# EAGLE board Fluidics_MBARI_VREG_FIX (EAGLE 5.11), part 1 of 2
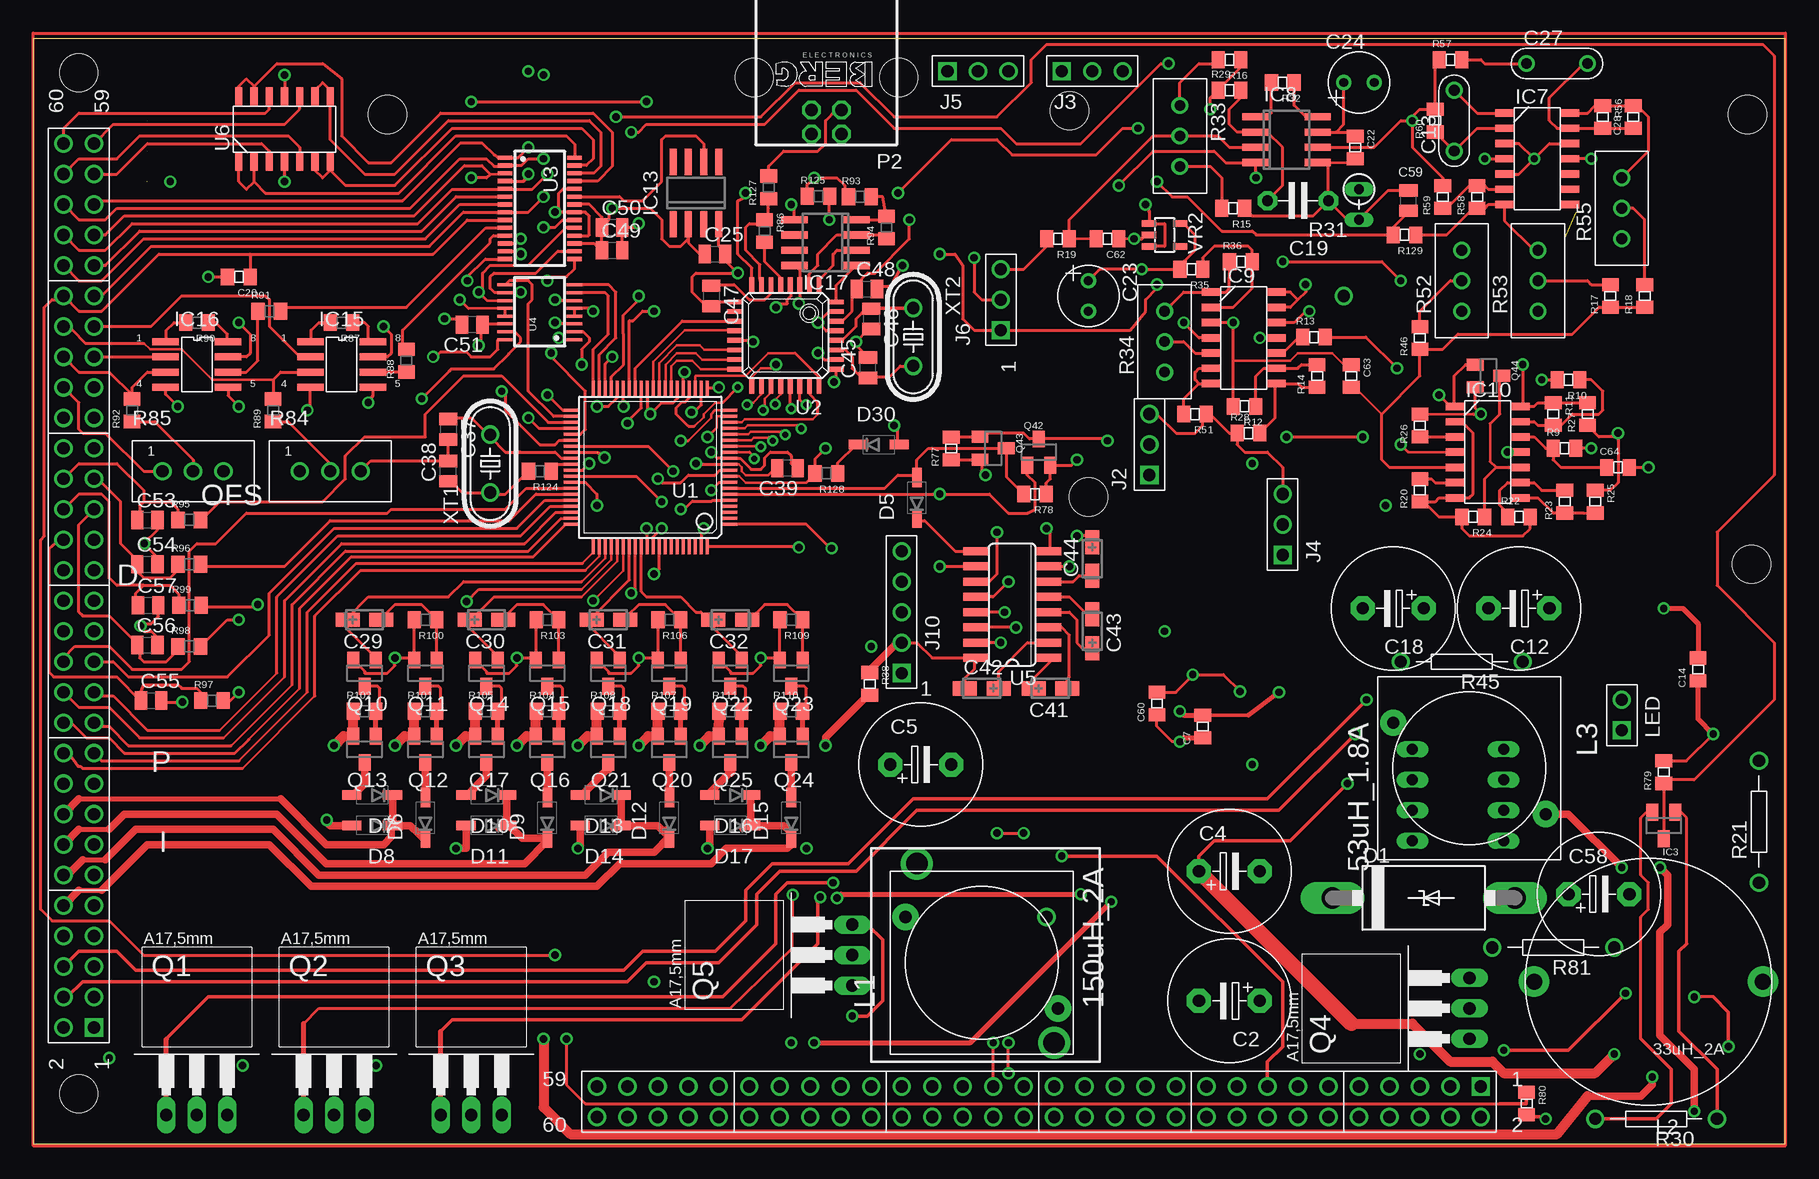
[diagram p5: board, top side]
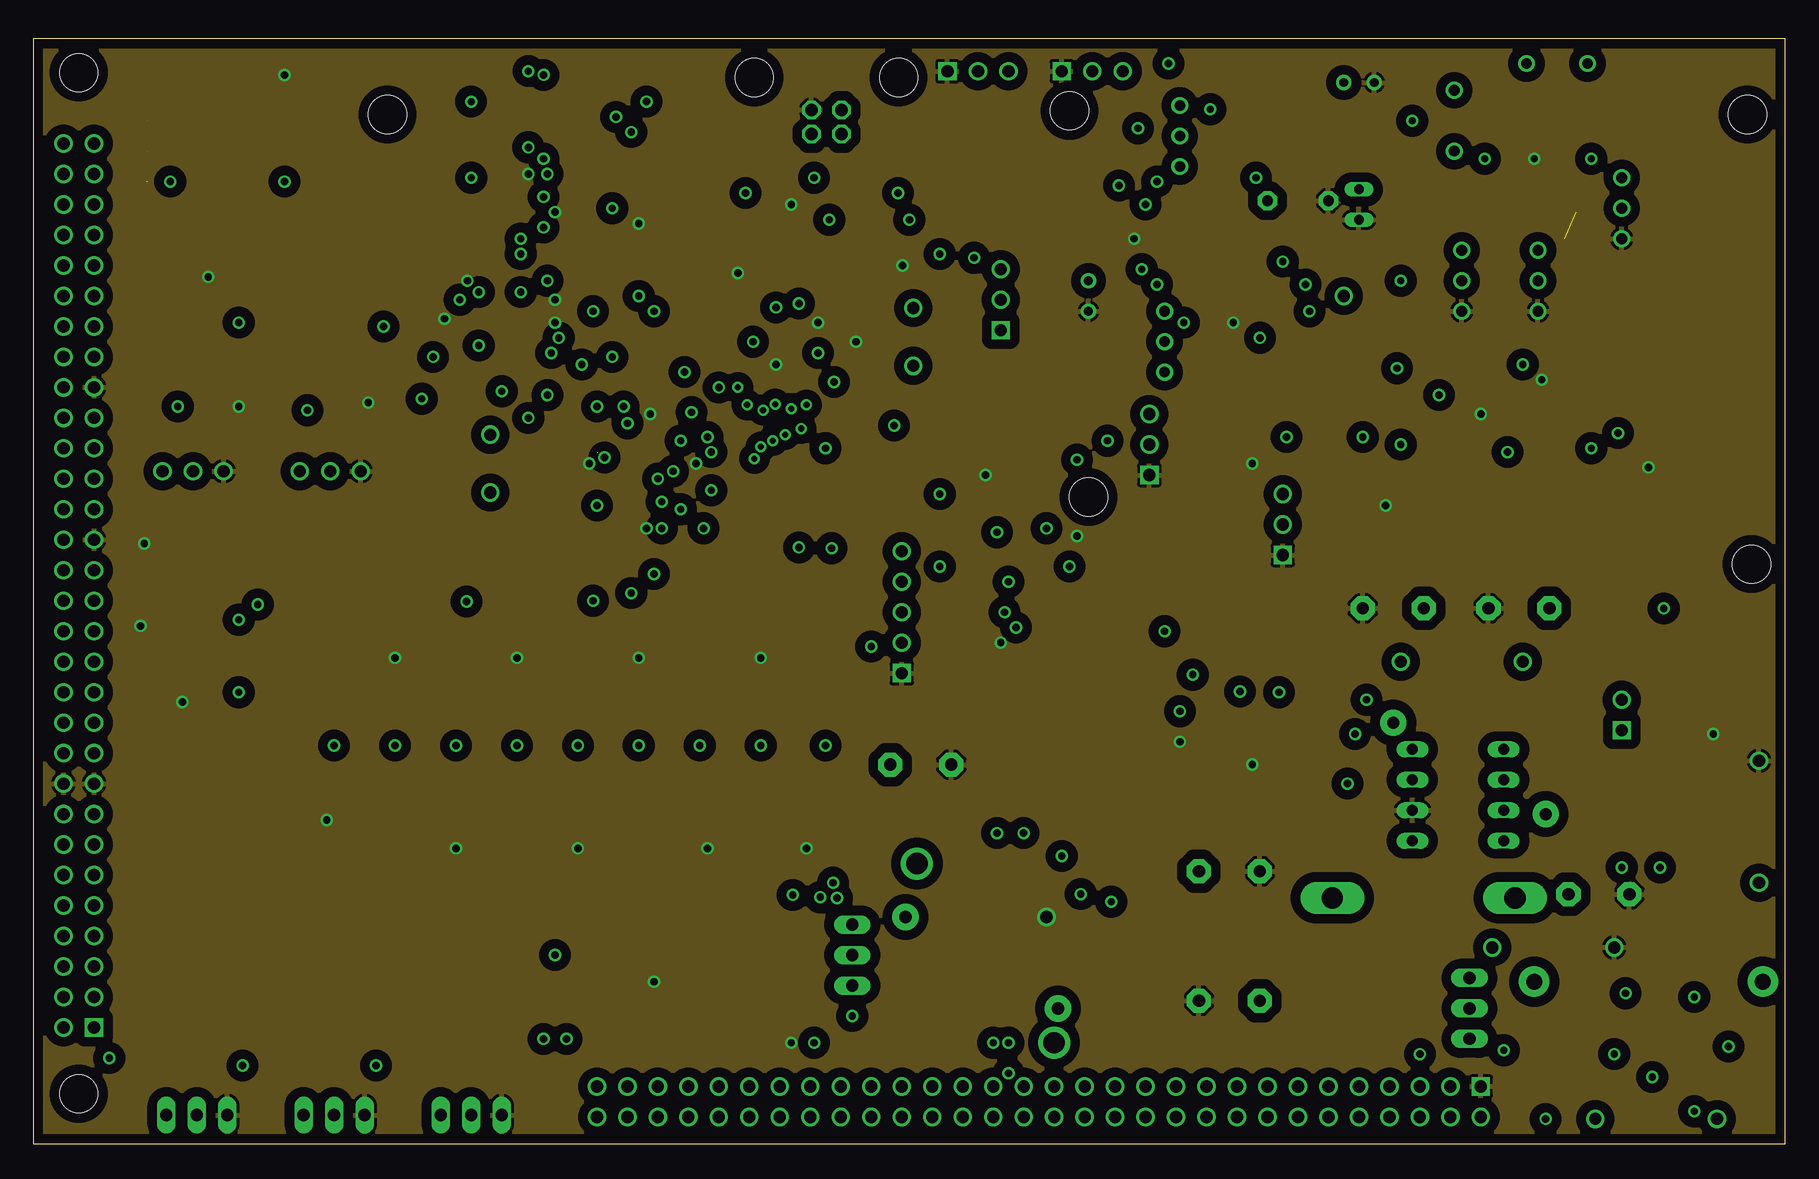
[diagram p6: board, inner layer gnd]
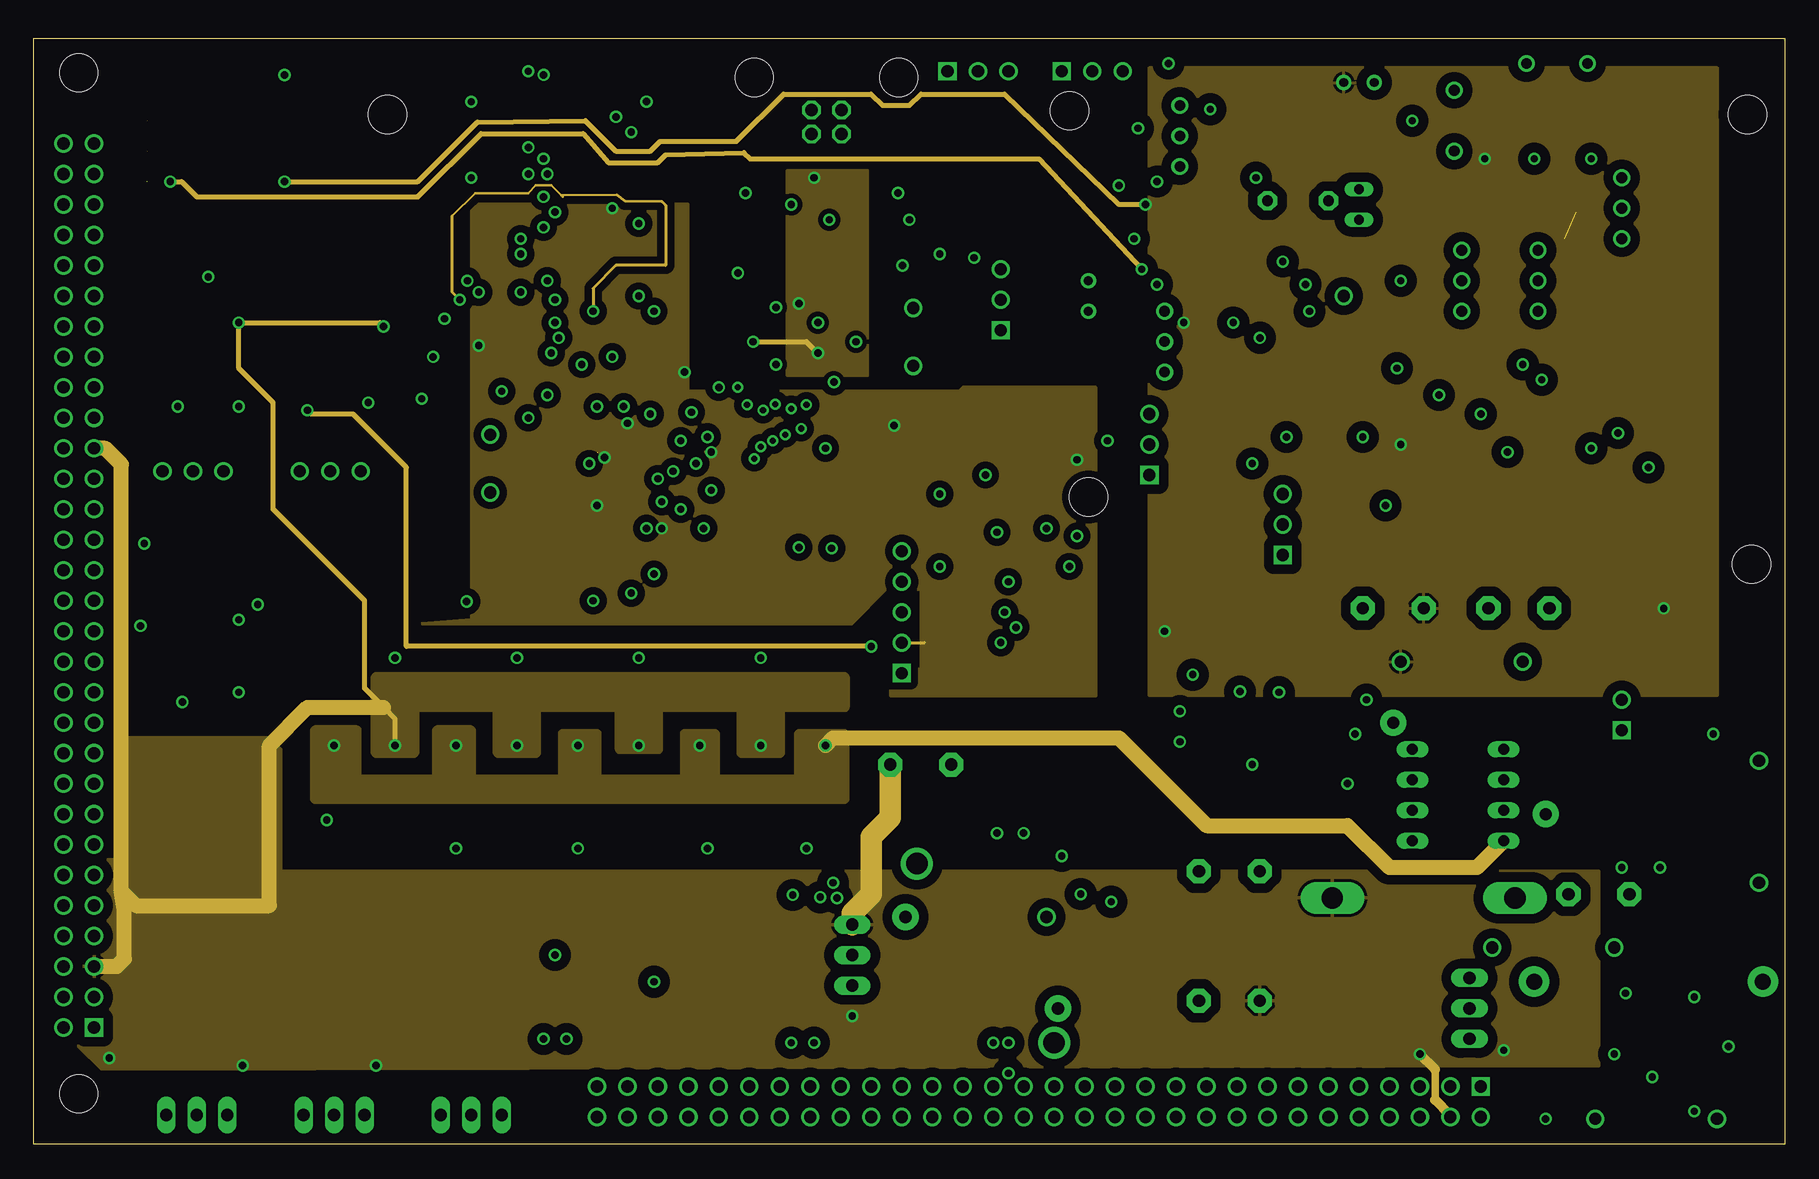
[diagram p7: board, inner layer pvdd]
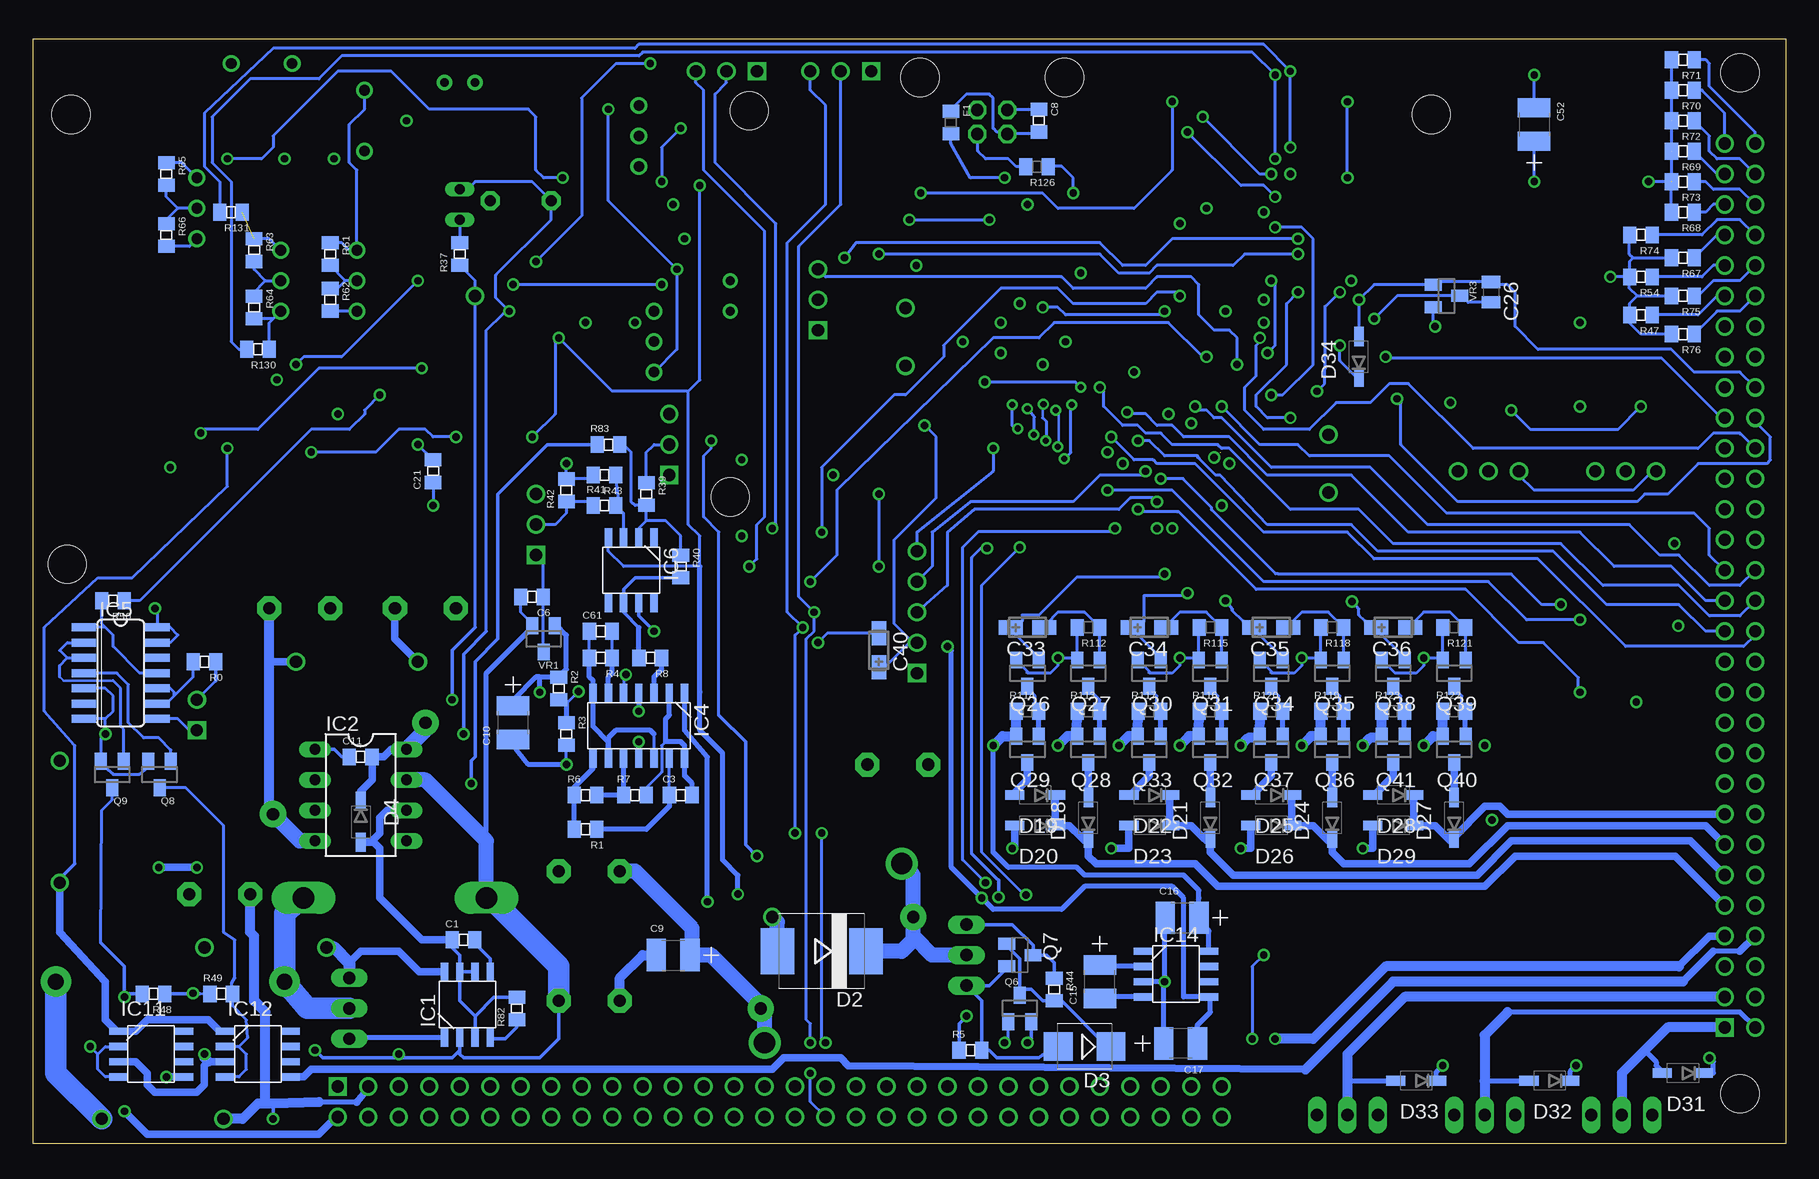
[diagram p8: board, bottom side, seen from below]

Size 146.03 x 92.06 mm. Coordinates in mm from the lower left corner, seen from the top.
Outline: 0,0 146.03,0 146.03,92.06 0,92.06 0,0
Copper layers (1*2*3*16): Top 0.035mm / dielectric 1.5mm / gnd 0.035mm / dielectric 0.15mm / pvdd 0.035mm / dielectric 0.2mm / Bottom 0.035mm
Design rules "default *": minimum track width 6mil, minimum drill 20mil, track to track 8mil, track to pad 8mil, pad to pad 7mil, via to via 7mil, smd to smd 0mil, copper to edge 8mil, drill to drill 6mil, minimum pad ring 8mil, minimum via ring 8mil, stop-mask expansion 0mil, vias tented up to drill 0mil, thermal gap 10mil
Net classes: 0 default: width 0.254 mm; 2 +5V: width 0.203 mm, drill 0.508 mm, clearance 0.203 mm
Holes 3.17 mm at 29.52,85.75 86.36,86.07 87.94,53.87 143.19,48.29 142.87,85.75 3.81,4.15 3.81,89.24

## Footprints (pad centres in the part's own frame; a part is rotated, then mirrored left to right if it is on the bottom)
0805 = smd 1.092 x 1.397: 1 -0.94,0; 2 0.94,0
ES-5 = drill 1.016 pad 2.007 octagon: 1 -2.54,0; 2 2.54,0
POLCAP1210 = smd 1.6 x 2.7: 1 -1.4,0; 2 1.4,0
C200 = drill 0.889 pad 1.397 round: 1 0,0; 2 5.08,0
C-5 = drill 0.889 pad 1.6 octagon: 1 -2.54,0; 2 2.54,0
C100P = drill 0.737 pad 1.27 round: + 0,0; - 2.54,0
C0805 = smd 1.016 x 1.524: 1 -0.85,0; 2 0.85,0
CT3216 = smd 2 x 1.2: + 1.4,0; - -1.4,0
C4111-15 = drill 1.778 long: A 7.62,0; C -7.62,0
SMC = smd 2.8 x 3.8: A 3.7,0; C -3.7,0
SMB = smd 2.4 x 2.4: A 2.2,0; C -2.2,0
SOD123 = smd 1.6 x 0.8: 1 -1.7,0; 2 1.7,0
SO8 = smd 1.524 x 0.61: 1 1.067,5.08; 2 1.067,3.81; 3 1.067,2.54; 4 1.067,1.27; 5 6.553,1.27; 6 6.553,2.54; 7 6.553,3.81; 8 6.553,5.08
DIL8 = drill 0.889 long: 1 -3.81,7.62; 2 -3.81,5.08; 3 -3.81,2.54; 4 -3.81,0; 5 3.81,0; 6 3.81,2.54; 7 3.81,5.08; 8 3.81,7.62
SOT23 = smd 1 x 1.4: 1 -0.95,-1.1; 2 0.95,-1.1; 3 0,1.1
SO-14 = smd 0.61 x 1.524: 1 -3.81,-2.794; 2 -2.54,-2.794; 3 -1.27,-2.794; 4 0,-2.794; 5 1.27,-2.794; 6 2.54,-2.794; 7 3.81,-2.794; 8 3.81,2.667; 9 2.54,2.667; 10 1.27,2.667; 11 0,2.667; 12 -1.27,2.667; 13 -2.54,2.667; 14 -3.81,2.667
SO14 = smd 0.66 x 2.032: 1 -3.81,-3.073; 2 -2.54,-3.073; 3 -1.27,-3.073; 4 0,-3.073; 5 1.27,-3.073; 6 2.54,-3.073; 7 3.81,-3.073; 8 3.81,3.073; 9 2.54,3.073; 10 1.27,3.073; 11 0,3.073; 12 -1.27,3.073; 13 -2.54,3.073; 14 -3.81,3.073
SO-8 = smd 0.61 x 1.524: 1 -1.27,-2.743; 2 0,-2.743; 3 1.27,-2.743; 4 2.54,-2.743; 5 2.54,2.743; 6 1.27,2.743; 7 0,2.743; 8 -1.27,2.743
INA141SOIC = smd 2.2 x 0.6: 1 2.48,5.715; 2 2.48,4.445; 3 2.48,3.175; 4 2.48,1.905; 5 7.68,1.905; 6 7.68,3.175; 7 7.68,4.445; 8 7.68,5.715
DUALFET1 = smd 1.524 x 0.61: 1 -2.743,2.54; 2 -2.743,1.27; 3 -2.743,0; 4 -2.743,-1.27; 5 2.743,-1.27; 6 2.743,0; 7 2.743,1.27; 8 2.743,2.54
SO8' = smd 0.6 x 2.2: 1 -1.905,-2.6; 2 -0.635,-2.6; 3 0.635,-2.6; 4 1.905,-2.6; 5 1.905,2.6; 6 0.635,2.6; 7 -0.635,2.6; 8 -1.905,2.6
INA141SOIC' = smd 2.2 x 0.6: 1 -2.6,1.905; 2 -2.6,0.635; 3 -2.6,-0.635; 4 -2.6,-1.905; 5 2.6,-1.905; 6 2.6,-0.635; 7 2.6,0.635; 8 2.6,1.905
SO-08 = smd 0.6 x 2.2: 1 -1.905,-2.6; 2 -0.635,-2.6; 3 0.635,-2.6; 4 1.905,-2.6; 5 1.905,2.6; 6 0.635,2.6; 7 -0.635,2.6; 8 -1.905,2.6
JUMP3 = drill 1.016 pad 1.524 square: 1 -2.54,0 | drill 1.016 pad 1.524 round: 2 0,0; 3 2.54,0
1X3 = drill 1.016 pad 1.524 square: 1 -2.54,0 | drill 1.016 pad 1.524 round: 2 0,0; 3 2.54,0
IDC3 = drill 1.016 square: 1 0,0 | drill 1.016 round: 2 2.54,0; 3 5.08,0
1X5 = drill 1.016 pad 1.524 square: 1 -5.08,0 | drill 1.016 pad 1.524 round: 2 -2.54,0; 3 0,0; 4 2.54,0; 5 5.08,0
INDUCTOR1 = drill 1.016 pad 2.184 round: P$1 3.81,1.27; P$2 11.43,13.97
INDUCTOR2 = drill 1.321 pad 2.54 round: P$1 -9.525,0; P$2 9.525,0
1X2 = drill 1.016 pad 1.524 square: 1 1.27,1.27 | drill 1.016 pad 1.524 round: 2 3.81,1.27
IDC60 = drill 1.016 square: 1 1.27,1.27 | drill 1.016 round: 2 1.27,3.81; 3 3.81,1.27; 4 3.81,3.81; 5 6.35,1.27; 6 6.35,3.81; 7 8.89,1.27; 8 8.89,3.81; 9 11.43,1.27; 10 11.43,3.81; 11 13.97,1.27; 12 13.97,3.81; 13 16.51,1.27; 14 16.51,3.81; 15 19.05,1.27; 16 19.05,3.81; 17 21.59,1.27; 18 21.59,3.81; 19 24.13,1.27; 20 24.13,3.81; 21 26.67,1.27; 22 26.67,3.81; 23 29.21,1.27; 24 29.21,3.81; 25 31.75,1.27; 26 31.75,3.81; 27 34.29,1.27; 28 34.29,3.81; 29 36.83,1.27; 30 36.83,3.81; 31 39.37,1.27; 32 39.37,3.81; 33 41.91,1.27; 34 41.91,3.81; 35 44.45,1.27; 36 44.45,3.81; 37 46.99,1.27; 38 46.99,3.81; 39 49.53,1.27; 40 49.53,3.81; 41 52.07,1.27; 42 52.07,3.81; 43 54.61,1.27; 44 54.61,3.81; 45 57.15,1.27; 46 57.15,3.81; 47 59.69,1.27; 48 59.69,3.81; 49 62.23,1.27; 50 62.23,3.81; 51 64.77,1.27; 52 64.77,3.81; 53 67.31,1.27; 54 67.31,3.81; 55 69.85,1.27; 56 69.85,3.81; 57 72.39,1.27; 58 72.39,3.81; 59 74.93,1.27; 60 74.93,3.81
PN61729 = drill 1.016 octagon: 1 1.25,4.71; 2 -1.25,4.71; 3 -1.25,2.71; 4 1.25,2.71 | hole 3.175: -6.02,0; 6.02,0
TO220 = drill 1.016 long: 1 -2.54,-6.35; 2 0,-6.35; 3 2.54,-6.35
SOT23-BEC = smd 1 x 1.4: B -0.95,-1.1; C 0,1.1; E 0.95,-1.1
R-10 = drill 1.016 pad 1.397 round: 1 -5.08,0; 2 5.08,0
RS-2,5 = drill 0.813 long: 1 -1.27,0; 2 1.27,0
TRIMPOT1 = drill 0.889 pad 1.397 round: 1 0,0; 2 5.08,0; 3 2.54,0
POT = drill 1.016 round: P$1 0,0; P$2 2.54,0; P$3 5.08,0
TQFP80 = smd 1.27 x 0.254: 1 -6.595,4.75; 2 -6.595,4.25; 3 -6.595,3.75; 4 -6.595,3.25; 5 -6.595,2.75; 6 -6.595,2.25; 7 -6.595,1.75; 8 -6.595,1.25; 9 -6.595,0.75; 10 -6.595,0.25; 11 -6.595,-0.25; 12 -6.595,-0.75; 13 -6.595,-1.25; 14 -6.595,-1.75; 15 -6.595,-2.25; 16 -6.595,-2.75; 17 -6.595,-3.25; 18 -6.595,-3.75; 19 -6.595,-4.25; 20 -6.595,-4.75; 41 6.595,-4.75; 42 6.595,-4.25; 43 6.595,-3.75; 44 6.595,-3.25; 45 6.595,-2.75; 46 6.595,-2.25; 47 6.595,-1.75; 48 6.595,-1.25; 49 6.595,-0.75; 50 6.595,-0.25; 51 6.595,0.25; 52 6.595,0.75; 53 6.595,1.25; 54 6.595,1.75; 55 6.595,2.25; 56 6.595,2.75; 57 6.595,3.25; 58 6.595,3.75; 59 6.595,4.25; 60 6.595,4.75 | smd 0.254 x 1.27: 21 -4.75,-6.595; 22 -4.25,-6.595; 23 -3.75,-6.595; 24 -3.25,-6.595; 25 -2.75,-6.595; 26 -2.25,-6.595; 27 -1.75,-6.595; 28 -1.25,-6.595; 29 -0.75,-6.595; 30 -0.25,-6.595; 31 0.25,-6.595; 32 0.75,-6.595; 33 1.25,-6.595; 34 1.75,-6.595; 35 2.25,-6.595; 36 2.75,-6.595; 37 3.25,-6.595; 38 3.75,-6.595; 39 4.25,-6.595; 40 4.75,-6.595; 61 4.75,6.595; 62 4.25,6.595; 63 3.75,6.595; 64 3.25,6.595; 65 2.75,6.595; 66 2.25,6.595; 67 1.75,6.595; 68 1.25,6.595; 69 0.75,6.595; 70 0.25,6.595; 71 -0.25,6.595; 72 -0.75,6.595; 73 -1.25,6.595; 74 -1.75,6.595; 75 -2.25,6.595; 76 -2.75,6.595; 77 -3.25,6.595; 78 -3.75,6.595; 79 -4.25,6.595; 80 -4.75,6.595
LQFP-32 = smd 0.4 x 1.2: 1 -2.8,-4.25; 2 -2,-4.25; 3 -1.2,-4.25; 4 -0.4,-4.25; 5 0.4,-4.25; 6 1.2,-4.25; 7 2,-4.25; 8 2.8,-4.25; 17 2.8,4.25; 18 2,4.25; 19 1.2,4.25; 20 0.4,4.25; 21 -0.4,4.25; 22 -1.2,4.25; 23 -2,4.25; 24 -2.8,4.25 | smd 1.2 x 0.4: 9 4.25,-2.8; 10 4.25,-2; 11 4.25,-1.2; 12 4.25,-0.4; 13 4.25,0.4; 14 4.25,1.2; 15 4.25,2; 16 4.25,2.8; 25 -4.25,2.8; 26 -4.25,2; 27 -4.25,1.2; 28 -4.25,0.4; 29 -4.25,-0.4; 30 -4.25,-1.2; 31 -4.25,-2; 32 -4.25,-2.8
TSSOP28 = smd 0.35 x 1.2: 1 -4.225,-2.9; 2 -3.575,-2.9; 3 -2.925,-2.9; 4 -2.275,-2.9; 5 -1.625,-2.9; 6 -0.975,-2.9; 7 -0.325,-2.9; 8 0.325,-2.9; 9 0.975,-2.9; 10 1.625,-2.9; 11 2.275,-2.9; 12 2.925,-2.9; 13 3.575,-2.9; 14 4.225,-2.9; 15 4.225,2.9; 16 3.575,2.9; 17 2.925,2.9; 18 2.275,2.9; 19 1.625,2.9; 20 0.975,2.9; 21 0.325,2.9; 22 -0.325,2.9; 23 -0.975,2.9; 24 -1.625,2.9; 25 -2.275,2.9; 26 -2.925,2.9; 27 -3.575,2.9; 28 -4.225,2.9
TSSOP16 = smd 0.254 x 1.27: 1 -2.275,-2.9; 2 -1.625,-2.9; 3 -0.975,-2.9; 4 -0.325,-2.9; 5 0.325,-2.9; 6 0.975,-2.9; 7 1.625,-2.9; 8 2.275,-2.9; 9 2.275,2.9; 10 1.625,2.9; 11 0.975,2.9; 12 0.325,2.9; 13 -0.325,2.9; 14 -0.975,2.9; 15 -1.625,2.9; 16 -2.275,2.9
SO16 = smd 0.66 x 2.032: 1 -4.445,-3.073; 2 -3.175,-3.073; 3 -1.905,-3.073; 4 -0.635,-3.073; 5 0.635,-3.073; 6 1.905,-3.073; 7 3.175,-3.073; 8 4.445,-3.073; 9 4.445,3.073; 10 3.175,3.073; 11 1.905,3.073; 12 0.635,3.073; 13 -0.635,3.073; 14 -1.905,3.073; 15 -3.175,3.073; 16 -4.445,3.073
SOT25 = smd 0.55 x 1.2: 1 -0.95,-1.3; 2 0,-1.3; 3 0.95,-1.3; 4 0.95,1.3; 5 -0.95,1.3
HC49/S = drill 1.016 round: 1 -2.413,0; 2 2.413,0

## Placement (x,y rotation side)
C1  0.1  [0805]  110.17,16.98 0 bottom
C2  100uF  [ES-5]  99.69,11.9 180 top
C3  .018  [0805]  92.07,29.05 0 bottom
C4  100uF  [ES-5]  99.69,22.7 0 top
C5  100uF  [ES-5]  73.97,31.59 0 top
C6  0.1uF  [0805]  104.45,45.55 180 bottom
C7  0.1uF  [0805]  97.47,34.76 90 top
C8  0.1uF  [0805]  62.22,85.24 270 bottom
C9  10uF  [POLCAP1210]  92.7,15.71 0 bottom
C10  10uF  [POLCAP1210]  106.04,35.08 90 bottom
C11  0.1uF  [0805]  118.74,32.22 0 bottom
C12  220uF  [ES-5]  123.82,44.6 180 top
C13  1uF  [C200]  118.42,82.7 90 top
C14  0.1  [0805]  138.74,39.52 90 top
C15  10uF  [POLCAP1210]  57.14,13.49 90 bottom
C16  10uF  [POLCAP1210]  50.29,18.82 0 bottom
C17  10uF  [POLCAP1210]  50.41,8.34 180 bottom
C18  220uF  [ES-5]  113.34,44.6 180 top
C19  0.47uF  [C-5]  105.41,78.57 180 top
C20  0.1uF  [0805]  17.14,72.22 180 top
C21  10uF  [0805]  112.71,56.03 90 bottom
C22  0.1uF  [0805]  110.17,83.02 270 top
C23  10uF  [C100P]  87.94,71.91 270 top
C24  10uF  [C100P]  109.22,88.42 0 top
C25  0.1uF  [C0805]  56.83,74.13 0 top
C26  0.1uF  [C0805]  24.54,70.95 270 bottom
C27  1.0uF  [C200]  124.45,90 0 top
C28  0.1uF  [0805]  133.34,85.56 90 top
C29  10uF  [CT3216]  27.62,43.65 180 top
C30  10uF  [CT3216]  37.78,43.65 180 top
C31  10uF  [CT3216]  47.94,43.65 180 top
C32  10uF  [CT3216]  58.1,43.65 180 top
C33  10uF  [CT3216]  63.18,43.02 180 bottom
C34  10uF  [CT3216]  53.02,43.02 180 bottom
C35  10uF  [CT3216]  42.86,43.02 180 bottom
C36  10uF  [CT3216]  32.7,43.02 180 bottom
C37  22pF  [C0805]  34.6,59.52 270 top
C38  22pF  [C0805]  34.6,56.03 90 top
C39  0.1uF  [C0805]  62.86,56.29 180 top
C40  10uF  [CT3216]  75.56,41.11 270 bottom
C41  10uF  [CT3216]  84.77,37.94 180 top
C42  10uF  [CT3216]  79.05,37.94 0 top
C43  10uF  [CT3216]  88.26,42.7 270 top
C44  10uF  [CT3216]  88.26,48.73 90 top
C45  22pF  [C0805]  69.58,64.66 90 top
C46  22pF  [C0805]  69.84,68.73 270 top
C47  33nF  [C0805]  56.51,70.64 270 top
C48  0.1uF  [C0805]  69.48,71.22 0 top
C49  0.1uF  [C0805]  48.25,74.45 0 top
C50  0.1uF  [C0805]  48.25,76.35 0 top
C51  0.1uF  [C0805]  36.6,68.24 180 top
C52  10uF  [POLCAP1210]  20.95,84.92 270 bottom
C53  0.1  [C0805]  9.52,51.97 0 top
C54  0.1  [C0805]  9.52,48.29 0 top
C55  0.1  [C0805]  9.84,36.92 0 top
C56  0.1  [C0805]  9.52,41.55 0 top
C57  0.1  [C0805]  9.58,44.86 0 top
C58  1000uF  [ES-5]  130.49,20.79 0 top
C59  0.1uF  [C0805]  114.61,78.57 90 top
C60  .1  [0805]  93.66,36.66 90 top
C61  .1  [0805]  98.74,42.7 0 bottom
C62  0.1uF  [0805]  89.53,75.4 180 top
C63  0.1uF  [0805]  109.85,63.97 270 top
C64  0.1  [0805]  132.08,56.35 0 top
D1  9_Amp_Shottky  [C4111-15]  115.88,20.47 0 top
D2  3_A Shottky  [SMC]  80.32,16.03 180 bottom
D3  1N5819HW  [SMB]  58.41,8.09 180 bottom
D4  1N5819HW  [SOD123]  118.74,26.82 270 bottom
D5  1N5819HW  [SOD123]  73.66,53.81 90 top
D6  1N5819HW  [SOD123]  32.7,27.14 90 top
D7  1N5819HW  [SOD123]  28.25,29.05 180 top
D8  1N5819HW  [SOD123]  28.25,26.51 180 top
D9  1N5819HW  [SOD123]  42.86,27.14 90 top
D10  1N5819HW  [SOD123]  37.78,29.05 180 top
D11  1N5819HW  [SOD123]  37.78,26.51 180 top
D12  1N5819HW  [SOD123]  53.02,27.14 90 top
D13  1N5819HW  [SOD123]  47.3,29.05 180 top
D14  1N5819HW  [SOD123]  47.3,26.51 180 top
D15  1N5819HW  [SOD123]  63.18,27.14 90 top
D16  1N5819HW  [SOD123]  58.1,29.05 180 top
D17  1N5819HW  [SOD123]  58.1,26.51 180 top
D18  1N5819HW  [SOD123]  58.1,27.14 90 bottom
D19  1N5819HW  [SOD123]  62.54,29.05 180 bottom
D20  1N5819HW  [SOD123]  62.54,26.51 180 bottom
D21  1N5819HW  [SOD123]  47.94,27.14 90 bottom
D22  1N5819HW  [SOD123]  53.02,29.05 180 bottom
D23  1N5819HW  [SOD123]  53.02,26.51 180 bottom
D24  1N5819HW  [SOD123]  37.78,27.14 90 bottom
D25  1N5819HW  [SOD123]  42.86,29.05 180 bottom
D26  1N5819HW  [SOD123]  42.86,26.51 180 bottom
D27  1N5819HW  [SOD123]  27.62,27.14 90 bottom
D28  1N5819HW  [SOD123]  32.7,29.05 180 bottom
D29  1N5819HW  [SOD123]  32.7,26.51 180 bottom
D30  1N5819HW  [SOD123]  70.48,58.26 0 top
D31  1N5819HW  [SOD123]  8.57,5.87 180 bottom
D32  1N5819HW  [SOD123]  19.68,5.23 180 bottom
D33  1N5819HW  [SOD123]  30.79,5.23 180 bottom
D34  [SOD123]  35.55,65.56 90 bottom
F1  FERRITE  [0805]  69.55,85.09 270 bottom
IC1  MAX1771ESA  [SO8]  106.68,7.77 90 bottom
IC2  LM2672-5  [DIL8]  118.74,25.23 0 bottom
IC3  ZXCT1009  [SOT23]  135.88,26.51 180 top
IC4  LT1802  [SO-14]  95.56,34.76 180 bottom
IC5  74HC14  [SO14]  138.74,39.2 270 bottom
IC6  MAX409  [SO-8]  95.56,47.78 180 bottom
IC7  TLC2254  [SO-14]  125.41,82.07 270 top
IC8  INA141  [INA141SOIC]  99.37,79.84 0 top
IC9  TLC2254  [SO-14]  100.96,67.14 270 top
IC10  TLC2254  [SO-14]  121.28,57.62 270 top
IC11  IRF7389  [DUALFET1]  136.2,6.82 0 bottom
IC12  IRF7389  [DUALFET1]  127.31,6.82 0 bottom
IC13  AD780  [SO8']  55.24,79.21 0 top
IC14  ICL7660  [SO8]  54.6,10.95 0 bottom
IC15  INA141  [INA141SOIC']  25.71,64.92 0 top
IC16  INA141  [INA141SOIC']  13.65,64.92 0 top
IC17  93-C46ASN  [SO-08]  66.04,75.08 90 top
J2  [JUMP3]  93.02,58.26 90 top
J3  [1X3]  88.26,89.37 0 top
J4  [1X3]  104.14,51.59 90 top
J5  [1X3]  78.73,89.37 0 top
J6  IDC3  [IDC3]  80.64,67.78 90 top
J10  [1X5]  72.39,44.29 90 top
L1  150uH_2A  [INDUCTOR1]  86.67,7.46 90 top
L2  33uH_2A  [INDUCTOR2]  134.62,13.49 180 top
L3  53uH_1.8A  [INDUCTOR1]  112.07,38.89 270 top
LED  1X2  [1X2]  133.66,33.17 90 top
P1  IDC60  [IDC60]  6.34,8.41 90 top
P2  USB_B  [PN61729]  66.11,88.85 180 top
P3  IDC60  [IDC60]  121.92,6.03 180 top
Q1  IRL3103L  [TO220]  13.65,8.73 0 top
Q2  IRL3103L  [TO220]  25.08,8.73 0 top
Q3  IRL3103L  [TO220]  36.51,8.73 0 top
Q4  IRL3103L  [TO220]  113.34,11.27 90 top
Q5  IRF4905L  [TO220]  61.91,15.71 90 top
Q6  BSS138  [SOT23]  63.81,11.27 0 bottom
Q7  FMMT491  [SOT23-BEC]  63.81,15.71 270 bottom
Q8  BSS138  [SOT23]  135.5,30.76 180 bottom
Q9  BSS138  [SOT23]  139.44,30.76 180 bottom
Q10  BSS138  [SOT23]  27.62,39.2 180 top
Q11  BSS138  [SOT23]  32.7,39.2 180 top
Q12  IRML6402  [SOT23]  32.7,32.86 180 top
Q13  IRML6402  [SOT23]  27.62,32.86 180 top
Q14  BSS138  [SOT23]  37.78,39.2 180 top
Q15  BSS138  [SOT23]  42.86,39.2 180 top
Q16  IRML6402  [SOT23]  42.86,32.86 180 top
Q17  IRML6402  [SOT23]  37.78,32.86 180 top
Q18  BSS138  [SOT23]  47.94,39.2 180 top
Q19  BSS138  [SOT23]  53.02,39.2 180 top
Q20  IRML6402  [SOT23]  53.02,32.86 180 top
Q21  IRML6402  [SOT23]  47.94,32.86 180 top
Q22  BSS138  [SOT23]  58.1,39.2 180 top
Q23  BSS138  [SOT23]  63.18,39.2 180 top
Q24  IRML6402  [SOT23]  63.18,32.86 180 top
Q25  IRML6402  [SOT23]  58.1,32.86 180 top
Q26  BSS138  [SOT23]  63.18,39.2 180 bottom
Q27  BSS138  [SOT23]  58.1,39.2 180 bottom
Q28  IRML6402  [SOT23]  58.1,32.86 180 bottom
Q29  IRML6402  [SOT23]  63.18,32.86 180 bottom
Q30  BSS138  [SOT23]  53.02,39.2 180 bottom
Q31  BSS138  [SOT23]  47.94,39.2 180 bottom
Q32  IRML6402  [SOT23]  47.94,32.86 180 bottom
Q33  IRML6402  [SOT23]  53.02,32.86 180 bottom
Q34  BSS138  [SOT23]  42.86,39.2 180 bottom
Q35  BSS138  [SOT23]  37.78,39.2 180 bottom
Q36  IRML6402  [SOT23]  37.78,32.86 180 bottom
Q37  IRML6402  [SOT23]  42.86,32.86 180 bottom
Q38  BSS138  [SOT23]  32.7,39.2 180 bottom
Q39  BSS138  [SOT23]  27.62,39.2 180 bottom
Q40  IRML6402  [SOT23]  27.62,32.86 180 bottom
Q41  IRML6402  [SOT23]  32.7,32.86 180 bottom
Q42  BSS84  [SOT23]  83.81,57.62 0 top
Q43  BSS138  [SOT23]  80.01,57.94 270 top
Q44  BSS84  [SOT23]  121.28,63.97 270 top
R0  470  [0805]  131.76,40.16 180 bottom
R1  3K  [0805]  100.01,26.19 180 bottom
R2  10K  [0805]  102.23,37.94 270 bottom
R3  10K  [0805]  101.59,34.12 270 bottom
R4  10K  [0805]  98.74,40.48 180 bottom
R5  380  [0805]  67.94,7.77 0 bottom
R6  11K  [0805]  100.01,29.05 0 bottom
R7  10K  [0805]  95.88,29.05 0 bottom
R8  10K  [0805]  94.61,40.48 180 bottom
R9  4.7K  [0805]  127.63,57.94 0 top
R10  3.0K  [0805]  127.95,63.65 180 top
R11  27.0K  [0805]  126.68,60.8 270 top
R12  20.0K  [0805]  100.96,61.43 180 top
R13  20K  [0805]  106.74,67.21 0 top
R14  100K  [0805]  106.99,63.97 90 top
R15  3.0K  [0805]  100.01,77.94 180 top
R16  3.0K  [0805]  99.69,90.32 180 top
R17  1.OM  [0805]  131.44,70.64 90 top
R18  1.0M  [0805]  134.3,70.64 90 top
R19  3.0K  [0805]  85.4,75.4 180 top
R20  20K  [0805]  115.56,54.45 90 top
R21  0.1  [R-10]  143.82,26.82 90 top
R22  20.0K  [0805]  123.82,52.22 0 top
R23  20.0K  [0805]  127.63,53.49 90 top
R24  20.0K  [0805]  120.01,52.22 180 top
R25  20.0K  [0805]  130.17,53.49 270 top
R26  20K  [0805]  115.56,59.84 90 top
R27  20.0K  [0805]  129.53,60.8 90 top
R28  3.0K  [0805]  101.28,59.21 0 top
R29  10.0K  [0805]  99.69,87.78 0 top
R30  .025_Ohm  [R-10]  135.25,2.06 180 top
R31  10K@25C  [RS-2,5]  110.48,78.26 270 top
R32  49.9  [0805]  104.14,88.42 180 top
R33  10K  [TRIMPOT1]  95.56,86.51 270 top
R34  10K  [TRIMPOT1]  94.29,64.29 90 top
R35  20.0K  [0805]  96.52,72.86 180 top
R36  20.0K  [0805]  100.64,73.49 0 top
R37  0_Ohm  [0805]  110.48,74.13 90 bottom
R38  1_Ohm  [0805]  69.72,38.32 270 top
R39  10K  [0805]  94.93,54.13 270 bottom
R40  OMIT  [0805]  92.07,48.09 270 bottom
R41  10K  [0805]  98.42,53.18 0 bottom
R42  100K  [0805]  101.59,54.45 90 bottom
R43  Optional  [0805]  98.42,55.72 180 bottom
R44  4.7k  [0805]  60.95,12.85 270 bottom
R45  1 Ohm  [R-10]  119.06,40.16 180 top
R46  1.0M  [0805]  115.56,67.14 90 top
R47  10K  [0805]  12.06,69.05 180 bottom
R48  4.7K  [0805]  136.01,12.47 180 bottom
R49  4.7K  [0805]  130.36,12.47 0 bottom
R50  4.7K  [0805]  139.38,45.24 180 bottom
R51  3.0K  [0805]  96.83,60.8 180 top
R52  10K  [TRIMPOT1]  119.06,69.37 90 top
R53  10K  [TRIMPOT1]  125.41,69.37 90 top
R54  10K  [0805]  12.06,72.22 180 bottom
R55  10K  [TRIMPOT1]  132.39,75.4 90 top
R56  10M  [0805]  130.81,85.56 270 top
R57  47K  [0805]  118.11,90.32 0 top
R58  100K  [0805]  120.33,78.89 90 top
R59  20.0K  [0805]  117.47,78.89 90 top
R60  10M  [0805]  116.84,85.24 90 top
R61  Optional  [0805]  121.28,74.13 270 bottom
R62  Optional  [0805]  121.28,70.32 270 bottom
R63  Optional  [0805]  127.63,74.45 270 bottom
R64  Optional  [0805]  127.63,69.68 270 bottom
R65  Optional  [0805]  134.93,80.8 270 bottom
R66  Optional  [0805]  134.93,75.72 270 bottom
R67  10K  [0805]  8.57,73.81 180 bottom
R68  10K  [0805]  8.57,77.62 180 bottom
R69  10K  [0805]  8.57,82.7 180 bottom
R70  10K  [0805]  8.57,87.78 180 bottom
R71  10K  [0805]  8.57,90.32 180 bottom
R72  10K  [0805]  8.57,85.24 180 bottom
R73  10K  [0805]  8.57,80.16 180 bottom
R74  10K  [0805]  12.06,75.72 180 bottom
R75  10K  [0805]  8.57,70.64 180 bottom
R76  10K  [0805]  8.57,67.46 180 bottom
R77  1K  [0805]  76.51,57.94 90 top
R78  4.7K  [0805]  83.5,54.13 180 top
R79  3.0K  [0805]  135.88,30.95 90 top
R80  30K  [0805]  124.45,3.33 270 top
R81  .025  [R-10]  126.68,16.35 180 top
R82  4.7K  [0805]  105.72,11.27 90 bottom
R83  100K  [0805]  98.1,58.26 0 bottom
R84  100k  [POT]  22.22,56.03 0 top
R85  100k  [POT]  10.79,56.03 0 top
R86  1k  [0805]  60.95,76.03 270 top
R87  GAIN  [0805]  25.71,68.41 180 top
R88  1k  [0805]  31.11,65.24 90 top
R89  100K  [0805]  20,61.11 90 top
R90  GAIN  [0805]  13.65,68.41 180 top
R91  1k  [0805]  19.68,69.37 0 top
R92  100K  [0805]  8.25,61.11 90 top
R93  10k  [0805]  68.89,78.89 0 top
R94  2.2k  [0805]  71.12,76.35 90 top
R95  10K  [0805]  13.01,51.97 0 top
R96  10K  [0805]  13.01,48.29 0 top
R97  10K  [0805]  14.92,36.92 0 top
R98  10K  [0805]  13.01,41.43 0 top
R99  10K  [0805]  13.08,44.86 0 top
R100  20K  [0805]  32.7,43.65 180 top
R101  4.7K  [0805]  32.7,36.03 0 top
R102  4.7K  [0805]  27.62,36.03 0 top
R103  20K  [0805]  42.86,43.65 180 top
R104  4.7K  [0805]  42.86,36.03 0 top
R105  4.7K  [0805]  37.78,36.03 0 top
R106  20K  [0805]  53.02,43.65 180 top
R107  4.7K  [0805]  53.02,36.03 0 top
R108  4.7K  [0805]  47.94,36.03 0 top
R109  20K  [0805]  63.18,43.65 180 top
R110  4.7K  [0805]  63.18,36.03 0 top
R111  4.7K  [0805]  58.1,36.03 0 top
R112  20K  [0805]  58.1,43.02 180 bottom
R113  4.7K  [0805]  58.1,36.03 0 bottom
R114  4.7K  [0805]  63.18,36.03 0 bottom
R115  20K  [0805]  47.94,43.02 180 bottom
R116  4.7K  [0805]  47.94,36.03 0 bottom
R117  4.7K  [0805]  53.02,36.03 0 bottom
R118  20K  [0805]  37.78,43.02 180 bottom
R119  4.7K  [0805]  37.78,36.03 0 bottom
R120  4.7K  [0805]  42.86,36.03 0 bottom
R121  20K  [0805]  27.62,43.02 180 bottom
R122  4.7K  [0805]  27.62,36.03 0 bottom
R123  4.7K  [0805]  32.7,36.03 0 bottom
R124  100  [0805]  42.22,56.03 180 top
R125  470  [0805]  65.45,78.94 0 top
R126  27  [0805]  62.39,81.41 180 bottom
R127  27  [0805]  61.3,79.69 90 top
R128  10k  [0805]  66.1,55.84 180 top
R129  10K  [0805]  114.3,75.72 180 top
R130  20K  [0805]  127.31,66.19 180 bottom
R131  20K  [0805]  129.53,77.62 180 bottom
U1  PIC18F8720  [TQFP80]  51.43,56.35 180 top
U2  FT245BM  [LQFP-32]  62.69,67.34 180 top
U3  AD7490  [TSSOP28]  42.22,77.94 270 top
U4  AD7398  [TSSOP16]  42.21,69.28 90 top
U5  MAX202  [SO16]  81.59,44.92 90 top
U6  TLC2254  [SO-14]  20.95,84.61 0 top
VR1  ZMR500FCT  [SOT23]  103.5,42.06 180 bottom
VR2  TS520533  [SOT25]  94.29,75.72 270 top
VR3  ZMR500FCT  [SOT23]  28.25,70.64 270 bottom
XT1  6_MHz  [HC49/S]  38.09,56.67 90 top
XT2  6_MHz  [HC49/S]  73.34,67.22 270 top

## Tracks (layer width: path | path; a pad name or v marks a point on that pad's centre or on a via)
1WIRE  (via drill 0.61)
  Top 0.254: 78.73,58.89 79.05,59.21 82.55,59.21 83.03,58.72 Q42.3 89.38,58.72 v89.53,58.57 | 78.73,58.89 Q43.1 | R77.2 78.73,58.88 78.73,58.89
  Top 0.305: v85.72,23.96 93.66,23.96 104.14,13.49 104.14,8.09 102.87,6.82 P3.15 102.87,4.6
  Bottom 0.254: v89.53,58.57 89.53,57.94 90.17,57.3 90.17,52.22 88.9,50.95 88.9,35.71
  Bottom 0.305: 88.9,35.71 86.67,33.49 86.67,24.92 v85.72,23.96
2.5V_REF
  Top 0.254: U3.23 48.87,78.91 49.21,78.57 50.79,78.57 52.38,80.16 52.38,83.65 52.7,83.97 55.24,83.97 55.88,83.34 IC13.6 55.88,81.75
5V_REF  (via drill 0.61)
  Top 0.203: 36.27,69.6 U4.12
  Top 0.254: v46.67,69.37 46.43,69.6 45.13,69.6 45.11,69.59 | v35.55,70.32 36.27,69.6 | 45.11,69.59 45.08,69.56 | 45.11,69.59 U4.5 45.11,69.08 45.08,69.05 45.11,69.02 U4.4 | U4.12 | U4.12 | U4.12 | U4.13 39.31,68.97 39.31,68.98 U4.12 | P1.44 3.81,61.75 3.81,59.52 4.12,59.21 6.03,59.21 9.2,56.03 R85.P$1
  pvdd 0.203: 44,79.02 43.17,79.84 41.9,79.84 41.27,79.21 36.82,79.21 34.92,77.3 | 44,79.02 44.13,78.89 | 44,79.02 48.64,79.08 49.34,78.51 52.38,78.51
  pvdd 0.254: v35.55,70.32 34.92,70.95 34.92,77.3 | v46.67,69.37 46.67,71.27 48.57,73.18 52.7,73.18 52.7,78.19 52.38,78.51
  Bottom 0.254: R85.P$1 11.11,56.03 12.69,54.45 20.95,54.45 22.22,55.72 R84.P$1 | 24.76,71.8 C26.1 | 24.76,71.8 28.99,71.8 29.21,71.59 VR3.1 34.29,71.59 v35.55,70.32 D34.2 | P1.44 3.81,64.29 7.62,64.29 9.52,66.19 20.63,66.19 22.54,68.1 22.54,70.95 23.17,71.59 24.44,71.59 24.76,71.91 24.76,71.8
+5V  (via drill 0.61)
  Top 0.203: 114.61,57.62 IC10.4
  Top 0.254: C22.1 110.17,83.97 110.48,84.29 108.58,84.29 | IC8.7 108.58,84.29 | C24.+ 109.22,84.92 108.58,84.29 | v120.96,82.07 IC7.4 | v20.95,80.16 U6.4 | IC9.4 97.15,67.14 v95.88,68.41 | v113.98,58.26 114.61,57.62 | v92.7,78.26 92.99,77.65 VR2.1 94.29,76.67 94.29,74.77 VR2.3
  Top 0.406: C14.2 138.74,43.33 137.47,44.6 v135.88,44.6
  pvdd 0.406: v92.7,78.26 90.48,78.26 80.96,87.46 73.97,87.46 73.02,86.51 70.8,86.51 69.84,87.46 62.54,87.46 58.61,83.53 52.26,83.53 51.43,82.7 48.57,82.7 46.03,85.24 37.02,85.12 32.06,80.16 v20.95,80.16
  Bottom 0.254: v20.95,80.16 C52.2 | v135.88,44.6 135.67,44.39 IC5.14 134.62,43.02 133.98,42.38 134.62,41.74 IC5.13 135.88,41.74 | C21.2 v113.98,58.26
  Bottom 0.305: IC6.7 95.56,43.97 v94.29,42.7
  Bottom 0.61: C18.1 115.88,42.06 R45.2
  pour pvdd (isolate 0.813): 93.02,37.3 93.02,89.69 140.33,89.69 140.33,37.3
+5V_B  (via drill 0.61)
  Top 0.254: 97.15,35.7 97.15,35.71 97.8,35.7
  Top 0.305: 97.8,35.7 101.27,35.7
  Top 0.406: C7.2 97.15,35.7 95.89,35.7 v95.56,36.03 | 101.27,35.7 v103.82,37.62
  Bottom 0.254: 102.55,43.33
  Bottom 0.305: 105.41,36.03 C10.2 106.04,36.98
  Bottom 0.406: 102.55,43.33 VR1.1 | IC4.4 v95.56,36.03 | 106.04,36.98 104.14,38.89 103.82,38.89 | 103.82,38.89 102.23,38.89 101.59,39.52 | 101.59,39.52 R2.1 | v103.82,37.62 103.82,38.89 | 101.59,39.52 101.59,42.38 102.55,43.33
+5V_IN  (via drill 0.61)
  Top 0.61: v138.43,2.69 138.43,6.18 135.57,9.04 135.57,17.62 136.2,18.25 136.2,22.38 v135.57,23.01 | v132.39,23.01 127.95,27.46 L3.P$2 | v66.04,33.17 66.04,33.87 69.54,37.38 R38.2
  Top 0.813: R111.1 57.14,34.12 Q25.2 56.34,33.95 v55.56,33.17 | R108.1 Q21.2 46.18,33.95 v45.4,33.17 | R105.1 Q17.2 36.02,33.95 v35.24,33.17 | R102.1 Q13.2 25.86,33.95 v25.08,33.17
  pvdd 1.27: v66.04,33.17 66.67,33.81 90.48,33.81 97.79,26.51 109.53,26.51 113.03,23.01 120.33,23.01 IC2.4
  Bottom 0.254: 48.89,18.57 C16.2 | 48.89,20.47
  Bottom 0.406: v66.04,33.17 66.04,24.28 64.77,23.01 59.05,23.01 58.41,22.38 50.16,22.38 48.89,21.11 48.89,20.47 | IC14.8 48.05,17.73 48.89,18.57 | C16.2 48.89,20.47
  Bottom 0.61: 126.36,40.16 R45.1 | P3.2 120.8,2.22 122.23,0.79 136.52,0.79 v138.43,2.69 | v132.39,23.01 v135.57,23.01
  Bottom 0.813: C12.1 126.36,40.16 126.36,27.78 L3.P$2 | R117.1 53.97,34.12 Q33.2 54.77,33.95 v55.56,33.17 | Q37.2 43.81,33.81 | 43.81,33.81 R120.1 | Q41.2 33.65,33.81 | 33.65,33.81 R123.1 | R114.1 64.13,34.12 Q29.2 65.25,33.95 v66.04,33.17 | 33.65,33.81 34.6,33.81 v35.24,33.17 | 43.81,33.81 44.76,33.81 v45.4,33.17
  Bottom 1.27: IC2.4 123.82,25.23 L3.P$2
  pour pvdd (isolate 0.61): 67.62,34.12 63.81,34.12 63.81,30.32 56.83,30.32 56.83,34.12 54.29,34.12 54.29,30.32 46.98,30.32 46.98,34.12 44.13,34.12 44.13,30.32 36.51,30.32 36.51,34.44 33.65,34.44 33.65,30.32 26.98,30.32 26.98,34.44 23.49,34.44 23.49,28.73 67.62,28.73
+12V  (via drill 0.61)
  Top 0.254: v29.21,68.1 29.84,67.46 29.84,65.88 29.52,65.56 IC15.7 28.25,65.56 | IC16.7 17.78,65.56 18.09,65.88 18.09,67.46 v17.14,68.41
  Top 0.305: v68.26,10.63 69.53,10.63 70.8,11.9 70.8,16.98 69.53,18.25 Q5.3 | v122.55,7.77 127.95,7.77 v132.71,12.54
  Top 0.813: R110.1 62.22,34.12 Q24.2 61.42,33.95 v60.64,33.17 | R107.1 Q20.2 51.26,33.95 v50.48,33.17 | R104.1 Q16.2 41.1,33.95 v40.32,33.17 | R101.1 Q12.2 30.94,33.95 v30.16,33.17
  pvdd 0.406: v29.21,68.1 28.89,68.41 v17.14,68.41 17.14,64.6 20,61.75 20,52.86 27.62,45.24 27.62,37.94 29.21,36.35 30.16,35.4 v30.16,33.17
  pvdd 0.61: 116.84,3.65 116.84,6.18
  pvdd 0.813: P3.4 118.11,2.38 116.84,3.65 | 116.84,6.18 v115.56,7.46
  pvdd 1.27: 29.21,36.35 22.86,36.35 19.68,33.17 19.68,19.84 8.57,19.84 7.36,21.04 | P1.39 6.03,57.94 7.36,56.6 7.36,21.04 | 7.36,21.04 7.62,19.52 7.62,15.39 6.98,14.76 P1.5
  pvdd 1.778: C5.1 71.43,27.14 69.84,25.55 69.84,20.79 68.26,19.2 Q5.3
  Bottom 0.254: C6.2 105.39,44.27 104.45,43.33 VR1.2 104.45,43.02 | R49.1 131.06,12.47 v132.71,12.54 | VR3.2 29.35,68.24 v29.21,68.1
  Bottom 0.305: C2.1 102.23,8.73 103.82,7.14 110.17,7.14 110.48,7.46 IC1.2 110.48,7.77 111.12,7.14 121.92,7.14 v122.55,7.77 | 62.71,16.03 Q7.C | 62.71,16.03 62.71,16.52 64.45,18.25 Q5.3 | R44.1 60.95,15.08 61.59,15.71 62.54,15.71 62.86,16.03 62.71,16.03 | R5.1 68.88,9.98 v68.26,10.63 | R48.1 132.14,12.47 v132.71,12.54
  Bottom 0.406: D32.1 17.98,5.98 v17.46,6.5 | D33.1 29.09,5.98 v28.57,6.5 | v6.34,7.14 6.03,6.82 6.03,5.87 D31.1 | 108.26,25.23 108.26,39.2 104.45,43.02
  Bottom 0.813: R113.1 59.05,34.12 Q28.2 59.85,33.95 v60.64,33.17 | R116.1 48.89,34.12 Q32.2 49.7,33.95 v50.48,33.17 | R119.1 38.73,34.12 Q36.2 39.53,33.95 v40.32,33.17 | R122.1 28.57,34.12 Q40.2 29.38,33.95 v30.16,33.17
  Bottom 1.27: IC2.7 113.34,30.32 108.26,25.23 D1.C
  Bottom 1.778: D1.C 107.95,20.47 102.23,14.76 C2.1
  pour pvdd (isolate 0.61): 67.62,36.35 62.22,36.35 62.22,32.54 59.05,32.54 59.05,36.35 52.06,36.35 52.06,32.86 48.89,32.86 48.89,36.35 41.9,36.35 41.9,32.54 38.73,32.54 38.73,36.35 31.75,36.35 31.75,32.54 28.57,32.54 28.57,38.89 67.62,38.89
  pour pvdd (isolate 0.813): 130.49,6.5 5.71,6.18 3.81,8.09 3.81,23.46 3.93,23.46 4.12,23.65 6.66,23.65 6.98,23.96 6.98,32.86 7.93,33.81 19.68,33.81 20.63,32.86 20.63,22.7 130.49,22.7
-5V_2  (via drill 0.61)
  Top 0.254: IC16.4 11.05,62.44 v12.06,61.43 | IC15.4 23.11,61.37 v22.86,61.11 | v102.23,67.14 IC9.11 | v101.91,80.48 101.85,80.54 IC8.4 99.37,81.75 98.42,82.7 93.34,82.7 v90.48,79.84 | v129.85,82.07 IC7.11 | v122.87,57.62 IC10.11 | v104.45,58.89 v110.8,58.89
  Top 0.406: v66.99,20.47 67.31,20.79 v87.31,20.79
  pvdd 0.406: v22.86,61.11 23.17,60.8 26.67,60.8 31.11,56.35 31.11,41.43 v69.84,41.43
  Bottom 0.254: 47.94,12.22 IC14.5 | IC6.4 98.1,49.37 96.83,48.09 90.48,48.09 90.48,50.63 91.44,51.59 91.44,62.7 | v22.86,61.11 21.27,59.52 13.96,59.52 v12.06,61.43 | v101.91,80.48 103.5,80.48 104.14,81.11 104.14,85.56 104.77,86.19 113.03,86.19 116.2,89.37 120.65,89.37 126.04,83.97 126.04,83.02 127,82.07 v129.85,82.07 | 91.44,62.7 90.48,63.65 v90.48,79.84 | v110.8,58.89 112.71,58.89 113.34,59.52 115.56,59.52 117.47,57.62 v122.87,57.62 | v104.45,58.89 102.55,60.8 102.55,66.83 v102.23,67.14 97.79,62.7 91.44,62.7
  Bottom 0.305: 90.48,37.62 90.48,37.3
  Bottom 0.406: C17.1 49.01,9.87 47.94,10.95 47.94,12.22 | IC14.5 50.16,12.22 50.16,20.47 51.11,21.43 58.41,21.43 60.32,19.52 66.04,19.52 v66.99,20.47 69.53,23.01 69.53,41.11 v69.84,41.43 | 90.48,48.09 90.48,37.62 90.48,34.44 88.58,32.54 88.58,23.65 87.31,22.38 v87.31,20.79
AD_NCS  (via drill 0.61)
  Top 0.254: U3.20 44.1,76.96 43.49,76.35 v42.54,76.35 | U1.41 44.14,61.1 v42.86,62.38
  Bottom 0.254: v42.86,62.38 41.9,62.38 39.36,64.92 39.36,75.4 40.32,76.35 v42.54,76.35
AN4  (via drill 0.61)
  Top 0.254: U3.9 36.17,76.96 33.33,74.13 18.09,74.13 | 18.09,74.13 10.47,74.13 5.71,69.37 3.81,69.37 P1.50 2.22,70.32 1.58,70.32 0.95,69.68 0.95,50.63 0.63,50.32 0.63,19.52 1.58,18.57 6.34,18.57 9.2,15.71 v43.49,15.71 | 122.23,3.33 46.03,3.33 44.45,4.92 v44.45,8.73 | C20.1 18.08,74.12 18.09,74.13
  Top 0.305: R80.1 124.44,3.31 122.23,3.33
  Bottom 0.254: R76.1 5.71,69.37 3.81,69.37 P1.50 | v44.45,8.73 44.45,14.76 v43.49,15.71
AN6
  Top 0.254: U3.7 39.36,78.27 39.36,78.26 35.55,78.26 32.7,75.4 9.2,75.4 5.71,71.91 3.81,71.91 P1.52
  Bottom 0.254: R75.1 7.62,70.32 6.03,71.91 3.81,71.91 P1.52
AN7
  Top 0.254: U3.6 35.26,78.91 32.38,76.03 8.88,76.03 6.03,73.18 P1.51
  Bottom 0.254: R54.1 6.98,72.22 6.03,73.18 P1.51
AN8  (via drill 0.61)
  Top 0.254: 39.36,79.53 U3.5 | 39.36,79.53 34.92,79.53 32.06,76.67 8.25,76.67 6.03,74.45 3.81,74.45 P1.54 | 135.88,30 IC3.3 | 39.36,79.53 41.59,79.53 v42.86,80.8 | v48.57,85.56 60.64,85.56 63.49,88.42 68.89,88.42 71.75,85.56 80.32,85.56 83.18,88.42 83.18,90.32 84.45,91.59 144.14,91.59 145.09,90.64 145.09,55.72 140.33,50.95 140.33,46.51 145.09,41.74 145.09,36.98 138.43,30.32 136.2,30.32 135.88,30 | 135.88,30 R79.1
  Bottom 0.254: R74.1 6.98,75.72 5.71,76.99 3.81,76.99 P1.54 | v42.86,80.8 43.81,80.8 v48.57,85.56
AN10  (via drill 0.6, 0.61)
  Top 0.254: P1.56 3.81,76.99 6.03,76.99 6.98,77.94 31.43,77.94 35.55,82.07 37.78,82.07 38.41,81.43 39.36,81.43 39.32,81.47 U3.2 40.72,81.52 41.27,82.07 v42.54,82.07
  Bottom 0.254: R73.1 6.66,80.16 6.03,79.53 3.81,79.53 P1.56 | v42.54,82.07 v42.54,89.05 44.45,90.96 95.25,90.96 95.56,90.64 120.33,90.64 122.23,88.73 127.95,88.73 131.12,85.56 131.12,81.75 129.53,80.16 129.55,66.84 128.9,66.19 R130.2
AN11  (via drill 0.6, 0.61)
  Top 0.254: P1.55 5.39,78.57 30.79,78.57 35.62,83.4 37.4,83.4 38.41,82.38 38.81,82.13 U3.1 40.41,82.16 v41.27,83.02
  Bottom 0.254: R68.1 6.66,77.62 6.03,78.26 P1.55 | R131.2 130.47,80.15 131.76,81.43 131.76,85.88 126.04,91.27 95.88,91.27 95.56,91.59 43.49,91.59 v41.27,89.37 v41.27,83.02
AN12
  Top 0.254: U3.28 45.12,83.29 44.45,83.97 35.24,83.97 30.48,79.21 19.36,79.21 18.41,80.16 | 18.41,80.16 U6.2 | 18.41,80.16 17.78,79.53 17.14,80.16 U6.1
AN13
  Top 0.254: U3.27 46.11,81.52 46.67,82.07 46.67,83.65 45.71,84.61 34.92,84.61 30.16,79.84 26.03,79.84 24.76,81.11 | 24.76,81.75 U6.7 24.76,81.11 | 24.76,81.11 24.12,80.48 23.49,81.11 U6.6 23.49,82.07
AN14
  Top 0.254: U3.26 46.73,80.86 47.3,81.43 47.3,84.29 46.35,85.24 34.6,85.24 30.16,80.8 27.62,80.8 24.76,83.65 U6.8 24.76,87.78 24.12,88.42 23.49,87.78 U6.9
AN15
  Top 0.254: U6.14 17.14,88.1 17.78,88.73 18.41,88.1 | 18.41,88.1 U6.13 | U3.25 47.04,80.21 48.25,81.43 48.25,84.29 46.67,85.88 33.97,85.88 29.84,81.75 27.94,81.75 25.71,83.97 25.71,88.73 24.12,90 20.32,90 18.41,88.1
AV1
  Bottom 0.254: Q26.3 63.18,37.94 62.54,37.3 62.54,36.03
  Bottom 0.406: 62.54,36.03 R114.2 62.24,34.43 62.54,34.12 62.37,33.95 Q29.1
AV2
  Bottom 0.254: Q30.3 53.02,37.94 52.38,37.3 52.38,36.03
  Bottom 0.406: 52.38,36.03 R117.2 52.08,34.43 52.38,34.12 52.21,33.95 Q33.1
AV3
  Bottom 0.254: Q34.3 42.86,37.94 42.22,37.3 42.22,36.03
  Bottom 0.406: 42.22,36.03 R120.2 41.92,34.43 42.22,34.12 42.05,33.95 Q37.1
AV4
  Bottom 0.254: Q38.3 32.7,37.94 32.06,37.3 32.06,36.03
  Bottom 0.406: 32.06,36.03 R123.2 31.76,34.43 32.06,34.12 31.89,33.95 Q41.1
AV5
  Top 0.254: Q10.3 28.72,38.11 28.89,37.94 28.89,36.03
  Top 0.406: 28.89,36.03 R102.2 28.56,33.81 28.57,33.81 | 28.57,33.81 | Q13.1 28.57,33.81
AV6
  Top 0.254: Q14.3 38.88,38.11 39.05,37.94 39.05,36.03
  Top 0.406: 39.05,36.03 R105.2 38.72,33.81 38.73,33.81 | 38.73,33.81 | Q17.1 38.73,33.81
AV7
  Top 0.254: Q18.3 49.04,38.11 49.21,37.94 49.21,36.03
  Top 0.406: 49.21,36.03 R108.2 48.88,33.81 48.89,33.81 | 48.89,33.81 | Q21.1 48.89,33.81
AV8
  Top 0.254: Q22.3 59.2,38.11 59.37,37.94 59.37,36.03
  Top 0.406: 59.37,36.03 R111.2 59.04,33.81 59.05,33.81 | 59.05,33.81 | Q25.1 59.05,33.81
AVCC  (via drill 0.61 pad 1.02)
  Top 0.254: R125.2 66.39,78.93 66.35,78.89 v66.35,76.99 | U2.30 67.43,68.54 68.26,69.37 68.26,70.64 68.63,71.01 C48.1 68.63,71.54 68.58,71.59 69.53,72.54 70.16,72.54 73.02,75.4 v73.02,76.99
  Bottom 0.254: v73.02,76.99 v66.35,76.99
D
  Top 0.254: R18.2 134.3,76.99 133.34,77.94 R55.3
  Bottom 0.254: R65.2 134.93,78.89 133.98,77.94 | R55.3 133.98,77.94 | R66.1 134.93,76.99 133.98,77.94
DA_NCS
  Top 0.254: U4.9 39.33,71.55 39.68,71.91 41.27,71.91 41.59,71.59 41.59,70.32 41.27,70 41.27,62.7 43.37,60.6 U1.42
DA_NLDAC
  Top 0.254: 46.67,62.96 U1.40 46.68,66.2 47.94,67.46 47.94,70.64 47.67,70.9 U4.7
DA_NRS
  Top 0.254: U1.39 47.18,65.75 48.57,67.14 48.57,70.95 47.97,71.55 U4.8
DA_OUT_B  (via drill 0.61)
  Top 0.254: U4.1 43.95,67 v43.81,67.14
  Bottom 0.254: v43.81,67.14 43.81,66.83 44.13,66.51 44.13,63.97 45.08,63.02 45.08,61.11 43.49,59.52 39.68,59.52 37.46,61.75 34.6,61.75 33.02,63.34 31.43,63.34 26.03,57.94 7.3,57.94 6.03,59.21 3.87,59.21 3.81,59.14 3.77,59.18 | P1.40 3.77,59.18 | 3.77,59.18 3.81,59.21 | 3.77,59.18
DA_OUT_C  (via drill 0.61)
  Top 0.254: v33.33,65.56 33.78,65.8 33.95,65.98 36.09,65.98 36.51,65.56 38.09,65.56 38.73,66.19 38.73,66.95 38.75,66.98 39.2,66.98 39.24,67.02 39.25,67 U4.16
  Bottom 0.254: P1.41 5.33,60.47 10.31,65.44 32.89,65.44 v33.33,65.56
DA_OUT_D  (via drill 0.61)
  Top 0.254: U4.15 40.13,67.65 40.63,67.14 40.63,66.83 39.68,65.88 39.64,65.8 38.4,64.55 34.84,64.55 34.67,64.38 34.6,64.29 v32.38,62.06
  Bottom 0.254: v32.38,62.06 32.06,61.75 32.06,58.26 27.3,53.49 12.38,53.49 11.74,54.13 9.84,54.13 7.3,56.67 1.58,56.67 1.27,56.98 1.27,58.89 2.54,60.16 P1.42
DB0  (via drill 0.51, 0.61)
  Top 0.203: 57.46,61.75 56.83,61.75 55.88,60.8 55.88,60.54 55.11,59.78
  Top 0.254: 57.46,61.75 v58.73,63.02 | 66.73,63.4 66.67,63.34 | v66.73,63.46 66.73,63.4 | U2.25 66.95,63.61 66.73,63.4 | 55.11,59.78 54.6,59.78 53.59,60.8 53.59,61.3 54.1,61.81 54.35,61.81 54.68,62.14 U1.24
  Bottom 0.254: v66.73,63.46 59.18,63.46 v58.73,63.02
DB1
  Top 0.203: U1.23 55.18,63.91 55.24,63.97 59.37,63.97 61.27,65.88 63.49,65.88
  Top 0.254: U2.24 65.47,63.09 65.47,63.9 63.49,65.88
DB2
  Top 0.203: U1.18 59.05,60.1 59.3,60.35 64.95,60.35 65.4,60.8
  Top 0.254: 65.4,60.8 65.4,61.75 64.77,62.38 64.77,63.02 U2.23
DB3  (via drill 0.51 pad 0.71)
  Top 0.203: U1.17 59.32,59.6 59.56,59.84 63.81,59.84
  Top 0.254: 64.07,59.59 64.13,59.52 | 64.07,59.59 v64,59.59 | 63.81,59.84 64.07,59.59 | v64.45,61.56 64.45,61.43 63.89,61.98 U2.22
  Bottom 0.254: v64,59.59 64.07,59.59 64.13,59.52 64.45,59.84 v64.45,61.56
DB4  (via drill 0.51 pad 0.71)
  Top 0.203: U1.16 59.58,59.1 59.81,59.33 62.41,59.33
  Top 0.254: 62.41,59.33 v62.67,59.08 | v63.18,61.24 63.18,61.11 63.09,61.2 U2.21
  Bottom 0.254: v62.67,59.08 62.54,59.21 62.61,59.27 62.61,60.54 63.11,61.18 63.18,61.11 v63.18,61.24
DB5  (via drill 0.51, 0.51 pad 0.71)
  Top 0.203: U1.15 59.84,58.6 60.07,58.83 61.34,58.83 | v61.84,61.62 61.84,62 62.29,62.45 U2.20
  Top 0.254: v61.65,58.57 61.59,58.57 61.34,58.83
  Bottom 0.203: 61.91,60.48 61.91,61.75
  Bottom 0.254: 61.91,61.75 61.84,61.81 v61.84,61.62 | 61.91,60.48 61.59,60.16 61.59,58.57 v61.65,58.57
DB6  (via drill 0.51, 0.51 pad 0.71)
  Top 0.203: U2.19 61.49,62.61 60.95,62.06 60.95,61.11 | U1.14 60.48,58.1
  Top 0.254: v60.83,61.11 60.95,61.11 | v60.64,58.06 60.64,58.26 60.48,58.1
  Bottom 0.203: 60.64,61.11 v60.83,61.11 | 60.57,58.32 60.57,61.05
  Bottom 0.254: 60.57,61.05 60.64,61.11 | v60.64,58.06 60.64,58.26 60.57,58.32
DB7  (via drill 0.51, 0.51 pad 0.61)
  Top 0.203: U1.13 59.7,57.6 60.1,57.21 | U2.18 60.7,62.44 60,61.75 59.68,61.75
  Top 0.254: 59.37,61.43 v59.49,61.56 59.68,61.75 | 59.7,57.6 59.68,57.62 | 60.1,57.21 v60.1,57.08
  Bottom 0.254: 59.49,61.62 59.37,61.75 | 59.49,61.62 v59.49,61.56 | 59.49,61.62 59.56,61.56 59.56,57.59 60.07,57.08 v60.1,57.08
EECS
  Top 0.254: IC17.1 68.58,73.18 66.95,71.55 U2.32
EEDATA
  Top 0.254: U2.2 64.7,72.47 65.4,73.18 65.4,74.13 66.99,75.72 IC17.3 70.48,75.72 70.8,75.4 R94.1
EEDOUT
  Top 0.254: IC17.4 70.48,76.99 70.8,77.3 R94.2 70.8,78.89 R93.2
EESK
  Top 0.254: U2.1 65.5,72 66.67,73.18 66.67,74.13 66.99,74.45 IC17.2
FET_SW1_CTRL  (via drill 0.61)
  Top 0.254: U1.79 55.68,51.08 v55.88,51.27
  Top 0.305: 11.11,8.73 14.6,12.22 57.46,12.22 61.91,16.66 61.91,20.79 62.86,21.74 v66.67,21.74
  Top 0.406: Q1.1 11.11,8.73
  Bottom 0.254: v55.88,51.27 56.26,51.02 67.24,51.02 68.58,49.68 68.58,23.65 v66.67,21.74
FET_SW2_CTRL  (via drill 0.61)
  Top 0.254: 22.54,10 23.81,11.27 58.1,11.27 63.24,16.28 v63.3,20.73 | U1.80 63.74,49.76 v63.81,49.68
  Top 0.406: Q2.1 22.54,10
  Bottom 0.254: v63.81,49.68 66.99,46.51 66.99,24.28 63.43,20.73 v63.3,20.73
FET_SW3_CTRL  (via drill 0.61)
  Top 0.254: v66.54,49.62 66.61,49.62 66.35,49.68 64.44,51.6 U1.1
  Top 0.305: 33.97,9.36 34.92,10.31 59.05,10.31 65.4,16.66 65.4,20.16
  Top 0.406: Q3.1 33.97,9.36 | v65.59,20.54 65.59,20.35 65.4,20.16
  Bottom 0.254: v66.54,49.62 67.05,49.62 67.81,48.86 67.81,24.16
  Bottom 0.305: 67.81,24.16 66.04,22.38 65.72,22.06 65.59,21.93 v65.59,20.54
GND  (via drill 0.61, 0.61 pad 0.71, 0.61 pad 1.02, 1.02)
  Top 0.203: U1.11 58.8,56.6 59.05,56.35 59.05,56.03 59.37,55.72 61.27,55.72 | U2.17 59.89,63.86 60.64,64.6 61.59,64.6 v61.91,64.92 | R26.2 120,60.78 | C62.1 v91.75,75.4 | C63.1 109.23,64.91 108.26,65.88 105.41,65.88 104.77,65.24 100.02,65.24 100.01,65.24
  Top 0.254: 62.22,40.48 62.23,40.48 Q23.2 62.23,40.47 62.22,40.48 | 62.22,40.48 v60.64,40.48 60.64,39.84 60,39.2 58.1,39.2 58.1,39.36 Q22.2 | 52.06,40.48 52.07,40.48 Q19.2 52.07,40.47 52.06,40.48 | 52.06,40.48 v50.48,40.48 50.48,39.84 49.84,39.2 47.94,39.2 47.94,39.36 Q18.2 | 41.9,40.48 41.91,40.48 Q15.2 41.91,40.47 41.9,40.48 | 41.9,40.48 v40.32,40.48 40.32,39.84 39.68,39.2 37.78,39.2 37.78,39.36 Q14.2 | 31.75,40.48 Q11.2 31.75,40.47 31.75,40.48 | 31.75,40.48 v30.16,40.48 30.16,39.84 29.52,39.2 27.62,39.2 27.62,39.36 Q10.2 | R109.2 62.24,40.49 62.22,40.48 | R106.2 52.08,40.49 52.06,40.48 | R103.2 41.92,40.49 41.9,40.48 | R100.2 31.76,40.49 31.75,40.48 | C37.2 C38.2 28.15,56.88 R84.P$3 | U1.70 51.18,51.2 v51.11,51.27 | U1.11 55.31,56.6 v55.24,56.67 | v50.48,76.67 50.16,76.35 C50.2 49.1,74.55 49.21,74.45 C49.2 | U2.29 66.08,67.73 v65.4,68.41 66.32,69.34 U2.31 | U3.4 40.9,80.21 v41.27,80.8 | U3.14 37.68,73.71 36.19,72.22 v36.19,71.91 | U1.31 51.18,61.05 v51.43,60.8 52.38,61.75 53.34,61.75 53.68,62.09 U1.26 | C39.2 61.97,56.29 61.91,56.35 61.27,55.72 | U1.51 45.78,56.1 v46.35,56.67 | C53.2 10.37,51.17 9.27,50.06 | 9.27,50.06 9.2,50 10.37,48.83 C54.2 | v9.27,50 9.27,50.06 | C57.2 10.43,43.93 9.84,43.33 8.88,43.33 8.95,43.27 v8.95,43.14 8.95,43.08 8.88,43.02 9.2,42.7 9.84,42.7 10.37,42.16 C56.2 | 10.85,36.6 10.69,36.77 C55.2 10.73,36.92 10.79,36.98 10.98,36.79 v12.44,36.79 | IC17.5 63.43,78 v63.18,78.26 | IC16.5 16.25,62.32 v17.14,61.43 | IC15.5 28.31,62.32 v27.94,61.75 | C51.2 35.7,68.55 35.55,68.41 35.24,68.73 v34.28,68.73 | C46.2 69.63,67.88 v68.58,66.83 68.58,66.51 C45.2 | C48.2 70.33,71.44 71.5,71.44 71.5,71.46 v72.45,73.18
  Top 0.254: U3.18 46.3,75.66 46.35,75.72 46.35,77.3 46.03,77.62 45.08,77.62 45.09,77.61 U3.21 v43.5,77.61 v43.49,77.62 43.81,77.94 43.81,79.21 44.16,79.56 U3.24 | U4.6 43.56,70.25 v43.49,70.32 | U4.3 43.6,68.3 v43.49,68.41 | v80.64,41.74 U5.15 | 57.78,74.13 C25.2 | IC13.4 57.14,74.77 57.78,74.13 | U2.9 56.96,70.13 56.51,69.68 C47.2 56.29,69.79 56.19,69.68 54.92,70.95 54.92,72.22 55.24,72.54 v58.73,72.54 57.78,73.49 57.78,74.13 | C19.1 106.68,77.3 101.59,77.3 100.96,77.94 R15.1 | C19.1 107.95,81.75 | 107.95,81.75 IC8.5 | C22.2 109.86,81.76 107.95,81.75 | v125.09,82.07 126.36,83.34 IC7.12 | IC7.5 123.82,80.8 v125.09,82.07 | IC7.3 123.82,83.34 v125.09,82.07 | 120,60.78 v120.65,60.8 120.18,61.26 Q44.2 | IC9.3 v100.01,68.41 100.02,68.4 100.02,65.24 R12.2 | C19.1 109.53,76.99 R31.2 112.92,79.42 C59.2 | R10.2 127.01,63.96 127,63.97 126.68,63.65 v125.73,63.65 | C44.+ 88.26,50.32 87.94,50.63 v86.99,50.63 | v20.95,89.05 U6.11 | 78.73,56.99 78.73,56.98 | 78.73,56.99 Q43.2 78.91,56.81 79.05,56.67 79.05,56.03 v79.37,55.72 | R77.1 78.73,57 78.73,56.99 | R79.2 137.78,31.89 v140.01,34.12 | v14.6,72.22 C20.2 | C60.1 93.66,34.76 94.93,33.49 v95.56,33.49 | 133.02,56.66 C64.2 v134.62,56.35
  Top 0.305: v91.75,75.4 92.39,75.4 92.7,75.72 VR2.2
  Top 0.406: C7.1 95.89,33.82 v95.56,33.49 | C14.1 138.74,35.4 v140.01,34.12
  Top 0.61: D17.2 56.4,24.6 v56.19,24.6 | D14.2 45.6,24.6 v45.4,24.6 | D11.2 36.08,24.6 v35.24,24.6 | D8.2 24.76,26.51 24.44,26.82
  Top 0.813: 24.44,26.82 24.47,26.85 v24.47,26.96
  Bottom 0.254: R121.2 28.56,40.49 28.57,40.48 28.57,40.47 Q39.2 28.74,40.48 v30.16,40.48 30.16,39.84 30.79,39.2 32.55,39.2 Q38.2 | R118.2 38.73,43.02 38.73,40.16 Q35.2 38.9,40.48 v40.32,40.48 40.32,39.84 40.95,39.2 42.86,39.2 42.86,39.36 Q34.2 | R115.2 48.89,43 Q31.2 49.06,40.48 v50.48,40.48 50.48,39.84 51.11,39.2 53.02,39.2 53.02,39.36 Q30.2 | Q26.2 63.18,39.36 63.18,39.2 61.27,39.2 60.64,39.84 v60.64,40.48 59.22,40.48 Q27.2 59.09,40.3 | 59.09,40.3 59.18,40.22 | R112.2 59.04,40.36 59.09,40.3 | 51.75,18.57 51.69,18.63 C16.1 | 51.81,13.42 v51.75,13.49 | 132.08,75.72 R55.1 133.02,74.78 R66.2 | R62.2 119.07,69.38 R52.1 | v63.18,8.41 62.86,8.73 | VR1.3 103.5,41.11 103.51,41.12 C6.1 103.51,48.43 J4.1 | C8.1 62.28,86.14 P2.4 | IC5.5 140.01,37.94 139.38,37.3 139.38,36.03 140.01,35.4 | 141.92,35.4 IC5.7 140.01,35.4 | C40.- 79.88,42.51 v80.64,41.74 | C26.2 26.45,70.1 26.98,70.64 VR3.3 32.38,70.64 v34.28,68.73 | R76.2 12.06,67.46 13.01,68.41 13.01,69.05 R47.2 13,70.02 12.38,70.64 | 12.38,70.64 13.01,71.27 13.01,72.22 R54.2 | 12.38,70.64 R75.2 | R54.2 13,73.51 12.69,73.81 | 12.69,73.81 13.01,74.13 13.01,75.72 R74.2 | 12.69,73.81 R67.2 | C52.1 v20.95,89.05 | 126.03,68.74 R64.2 | 126.03,68.74 R53.1 | 140.01,35.4 v140.01,34.12 140.39,33.75 Q9.2 140.39,31.65 139.38,30.76 137.16,30.76 136.52,31.27 136.52,31.9 136.48,31.86 Q8.2 | R43.2 99.06,55.72 99.39,55.38 R42.2 v101.59,56.67 | C21.1 v112.71,53.18 | R54.2 v14.6,72.22 | R31.2 R37.2 | v101.59,31.59 R3.2 | R130.1 126.37,68.4 126.03,68.74
  Bottom 0.305: 110.48,14.12 IC1.7 | IC1.6 110.28,14.33 110.33,14.28 | 110.48,14.12 110.33,14.28 | C1.1 111.11,16.33 110.48,15.71 110.48,14.44 110.33,14.28 | 110.33,14.28 | 110.48,14.12 110.48,11.9 109.22,10.63 | 109.22,8.73 IC1.3 109.22,10.63 | 62.86,8.73 Q6.2 | R82.2 107.64,12.21 109.22,10.63
  Bottom 0.406: 51.75,18.57 v51.75,13.49 IC14.3 | C17.2 51.81,13.42 | 95.56,31.9 IC4.11 v95.56,33.49 | C10.1 106.04,33.17 104.77,31.59 v101.59,31.59
  Bottom 0.61: D20.2 64.24,24.6 v64.45,24.6 | D23.2 54.72,24.6 v56.19,24.6 | D26.2 44.56,24.6 v45.4,24.6 | D29.2 34.4,24.6 v35.24,24.6 | 118.74,25.23 D4.2 117.9,25.12 117.79,25.23 | 117.79,25.23 117.15,25.87 117.15,27.14 116.52,27.78 IC2.6 | C1.1 113.66,16.98 117.15,20.47 117.15,24.6 117.79,25.23
  Bottom 0.813: C9.1 95.25,15.71 97.15,13.81 C2.2
  Bottom 1.27: D2.A 84.02,18.46 v84.45,18.89
  pour gnd (isolate 0.813): 146.05,91.91 146.05,-0.17 0.31,-0.17 0.31,91.91
I
  Top 0.254: R52.3 118.11,71.91 115.56,69.37 R46.2 115.56,67.78
  Bottom 0.254: R61.2 121.28,73.18 120.01,71.91 | R52.3 120.01,71.91 | R62.1 120.66,71.26 120.01,71.91
IC14
  Top 0.254: R90.2 11.74,68.41 11.11,67.78 11.11,67.14 10.79,66.83 IC16.1
IC15
  Top 0.254: IC15.8 28.25,66.83 27.94,67.14 27.94,68.1 27.62,68.41 R87.1
MCLR  (via drill 0.61)
  Top 0.203: U1.9 58.85,55.6 59.37,55.08 64.45,55.08
  Top 0.254: 64.45,55.08 65.16,55.79 R128.2 65.16,57.06 v66.04,57.94
  Bottom 0.254: J10.5 72.39,50.95 66.04,56.03 v66.04,57.94
N$1B
  Top 0.254: 40.63,57.62 43.49,57.62 44.01,57.1 U1.49 | 40.63,57.62 40.32,57.62 | C37.1 34.6,60.48 36.51,60.48 38.09,58.89 | 38.09,58.89 XT1.2 | 38.09,58.89 39.36,57.62 40.63,57.62
N$2B
  Top 0.254: 35.13,55.18 C38.1 34.6,55.4 35.75,54.25 XT1.1 38.09,54.13 39.36,54.13 41.27,56.03 R124.2
N$3
  Top 0.254: R124.1 43.74,56.6 U1.50
N$4B
  Top 0.254: XT2.2 72.77,64.79 72.26,64.79 71.38,63.92 69.58,63.92 | 69.58,63.92 69.53,63.97 68.89,63.97 68.26,64.6 68.26,65.56 67.68,66.13 U2.27 | 69.58,63.92 C45.1
N$5B
  Top 0.254: 70.17,69.62 70.23,69.62 | 70.16,69.68 70.17,69.68 70.17,69.62 | U2.28 67.41,66.93 68.58,68.1 68.58,68.73 69.53,69.68 69.84,69.68 C46.1 69.84,69.37 70.1,69.62 72.77,69.62 XT2.1 73.34,69.68 73.27,69.62 70.17,69.62
N$6
  Top 0.254: -0.01,92.54 146.05,92.54 146.05,-0.17 -0.01,-0.17 -0.01,92.54
N$10
  Bottom 0.61: D19.2 64.45,29.05 63.18,30.32 Q29.3
N$11
  Bottom 0.61: 58.1,28.73 D18.2 Q28.3
N$17
  Bottom 0.254: Q27.3 57.95,38.11 57.95,37.79 57.14,36.98 57.14,35.71
  Bottom 0.406: R113.2 57.16,35.73 57.14,35.71 57.14,33.81 57.15,33.81 Q28.1
N$18
  Top 0.254: IC10.13 125.09,60.16 125.4,59.86 R11.2 127.33,59.86 128.27,60.8 130.49,60.8 130.81,61.11 130.81,62.7 129.85,63.65 R10.1
N$20
  Bottom 0.254: Q27.1 57.14,40.16 | Q27.1 | Q27.1 57.14,43 R112.1 58.41,44.27 58.41,44.29 60.64,44.29 61.59,43.33 61.59,43.02 C33.-
N$21
  Top 0.254: R20.2 116.53,55.38 116.84,55.08 IC10.6
N$22  (via drill 0.61)
  Top 0.254: v129.85,57.94 R9.2
  Bottom 0.254: IC12.1 130.49,9.36 | 142.55,23.33 142.55,33.17 145.09,36.03 145.09,43.02 140.65,47.14 137.79,47.14 129.85,54.76 v129.85,57.94
  Bottom 0.305: R21.1 143.82,22.06 142.55,23.33
  Bottom 0.61: 130.49,9.36 131.44,10.31 136.52,10.31 137.47,9.36 IC11.1 139.06,9.36 140.01,10.31 140.01,13.49 143.82,17.62 R21.1
N$23
  Bottom 1.778: D1.A 125.09,19.2 L2.P$2 123.19,11.27 Q4.2
N$24
  Bottom 0.203: 139.38,38.57 143.5,38.57 143.82,38.89
  Bottom 0.254: IC5.2 143.19,41.74 143.82,41.11 143.19,40.48 | 143.19,40.48 IC5.3 | Q9.1 138.49,34.51 138.74,34.76 138.74,37.94 139.38,38.57 | 143.82,38.89 143.82,39.84 143.19,40.48
N$25
  Bottom 0.254: Q8.1 134.55,32.79 135.57,33.81 136.84,33.81 138.11,35.08 138.11,38.25 139.06,39.2 140.65,39.2 141.6,39.2
  Bottom 0.305: 140.65,39.2 IC5.4
N$26  (via drill 0.61)
  Top 0.254: 130.49,54.45 R25.1 131.44,54.45 132.08,55.08 v132.08,59.21 131.76,58.89 130.49,58.89 129.53,59.84 R27.1 | R13.2 111.06,67.21 v113.66,64.6
  Bottom 0.254: v113.66,64.6 122.23,64.6 127.31,59.52 131.76,59.52 v132.08,59.21
N$27
  Top 0.254: IC9.6 97.15,64.6 96.83,64.29 96.83,63.65 97.15,63.34 | 97.15,63.34 IC9.7 | R51.2 95.89,62.08 97.15,63.34
N$28  (via drill 0.61)
  Top 0.254: Q44.1 119.37,64.92 118.42,63.97 118.42,61.43 118.8,61.49 IC10.1 118.11,61.43 v117.15,62.38
  Bottom 0.254: R50.1 137.16,45.24 122.87,59.52 119.69,59.52 118.42,60.8 118.42,61.11 v117.15,62.38
N$29
  Top 0.254: IC10.9 123.95,54.95 123.82,55.08 | 123.82,55.08 122.87,55.08 122.23,54.45 122.23,53.18 123.19,52.22 R22.1 | R23.2 125.71,54.43 125.09,55.08 123.82,55.08
N$30
  Top 0.254: 123.82,53.81 IC10.8 125.41,53.81 126.67,52.55 R23.1 129.21,52.55 129.22,52.54 R25.2
N$31
  Bottom 0.61: D22.2 54.6,29.05 53.02,30.63 Q33.3
N$32
  Top 0.203: 121.43,56.84 121.43,59.99
  Top 0.254: 121.43,59.99 122.23,60.8 122.23,63.65 122.38,64.12 Q44.3 | 121.92,56.35 121.43,56.84 | 124.14,56.35 IC10.10 121.92,56.35 | R24.1 120.95,55.38 121.92,56.35
N$33
  Top 0.254: IC9.5 96.83,65.88 95.88,66.83 R34.3
N$34
  Top 0.203: C63.2 110.16,63.03 112.39,60.8
  Top 0.254: R18.1 131.45,69.7 R17.1 130.5,69.7 128.27,67.46 118.74,67.46 117.47,66.19 115.56,66.19 R46.1 115.56,63.97 112.39,60.8 112.39,56.98 113.03,56.35 IC10.5
N$35
  Bottom 0.305: 119.58,8.84 Q4.1
  Bottom 0.406: IC1.1 119.58,8.84
N$36
  Bottom 0.406: IC4.8 99.37,31.27 100.95,29.69 R6.1 100.96,29.05 100.95,29.03 R1.2
N$37
  Top 0.254: R32.2 103.2,85.89 102.87,85.56 IC8.1
N$39
  Top 0.254: R33.2 98.1,81.43 99.06,80.48 R15.2
N$40
  Top 0.254: R33.1 95.56,88.42 97.15,90 98.42,90 R16.2 | R16.2 99.06,90.64 | R16.2
N$42
  Top 0.254: IC9.10 103.63,65.75 104.14,65.88 105.47,67.21 R13.1
N$43
  Top 0.254: R26.1 115.56,58.89 IC10.3
N$44
  Top 0.254: IC10.12 125.09,58.89 126.04,57.94 R9.1 126.68,57.93 126.68,56.98 127.31,56.35 C64.1
N$45
  Top 0.254: R14.1 105.71,63.03 105.41,63.34 IC9.8 103.5,63.34 103.5,60.48 102.23,59.21 R28.2
N$46
  Bottom 0.254: C15.2 57.14,15.08 56.83,14.76
  Bottom 0.406: IC14.2 56.83,14.76
N$47
  Bottom 0.254: IC5.9 134.93,36.66 134.3,37.3 | 134.3,37.3 134.3,37.62 134.62,37.94 IC5.10 | R0.2 132.7,38.9 134.3,37.3
N$48
  Top 0.254: 101.58,73.18 101.58,71.26 100.01,69.68 IC9.2 98.1,69.68 | 101.58,73.18 R36.2 | R35.1 97.45,73.8 98.42,74.77 101.28,74.77 101.59,74.45 101.59,73.18 101.58,73.18
N$49
  Bottom 0.254: LED.1 133.03,34.44 133.98,35.4 IC5.8
N$50
  Bottom 0.254: C15.1 57.14,11.9 56.83,12.22
  Bottom 0.406: IC14.4 56.83,12.22
N$52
